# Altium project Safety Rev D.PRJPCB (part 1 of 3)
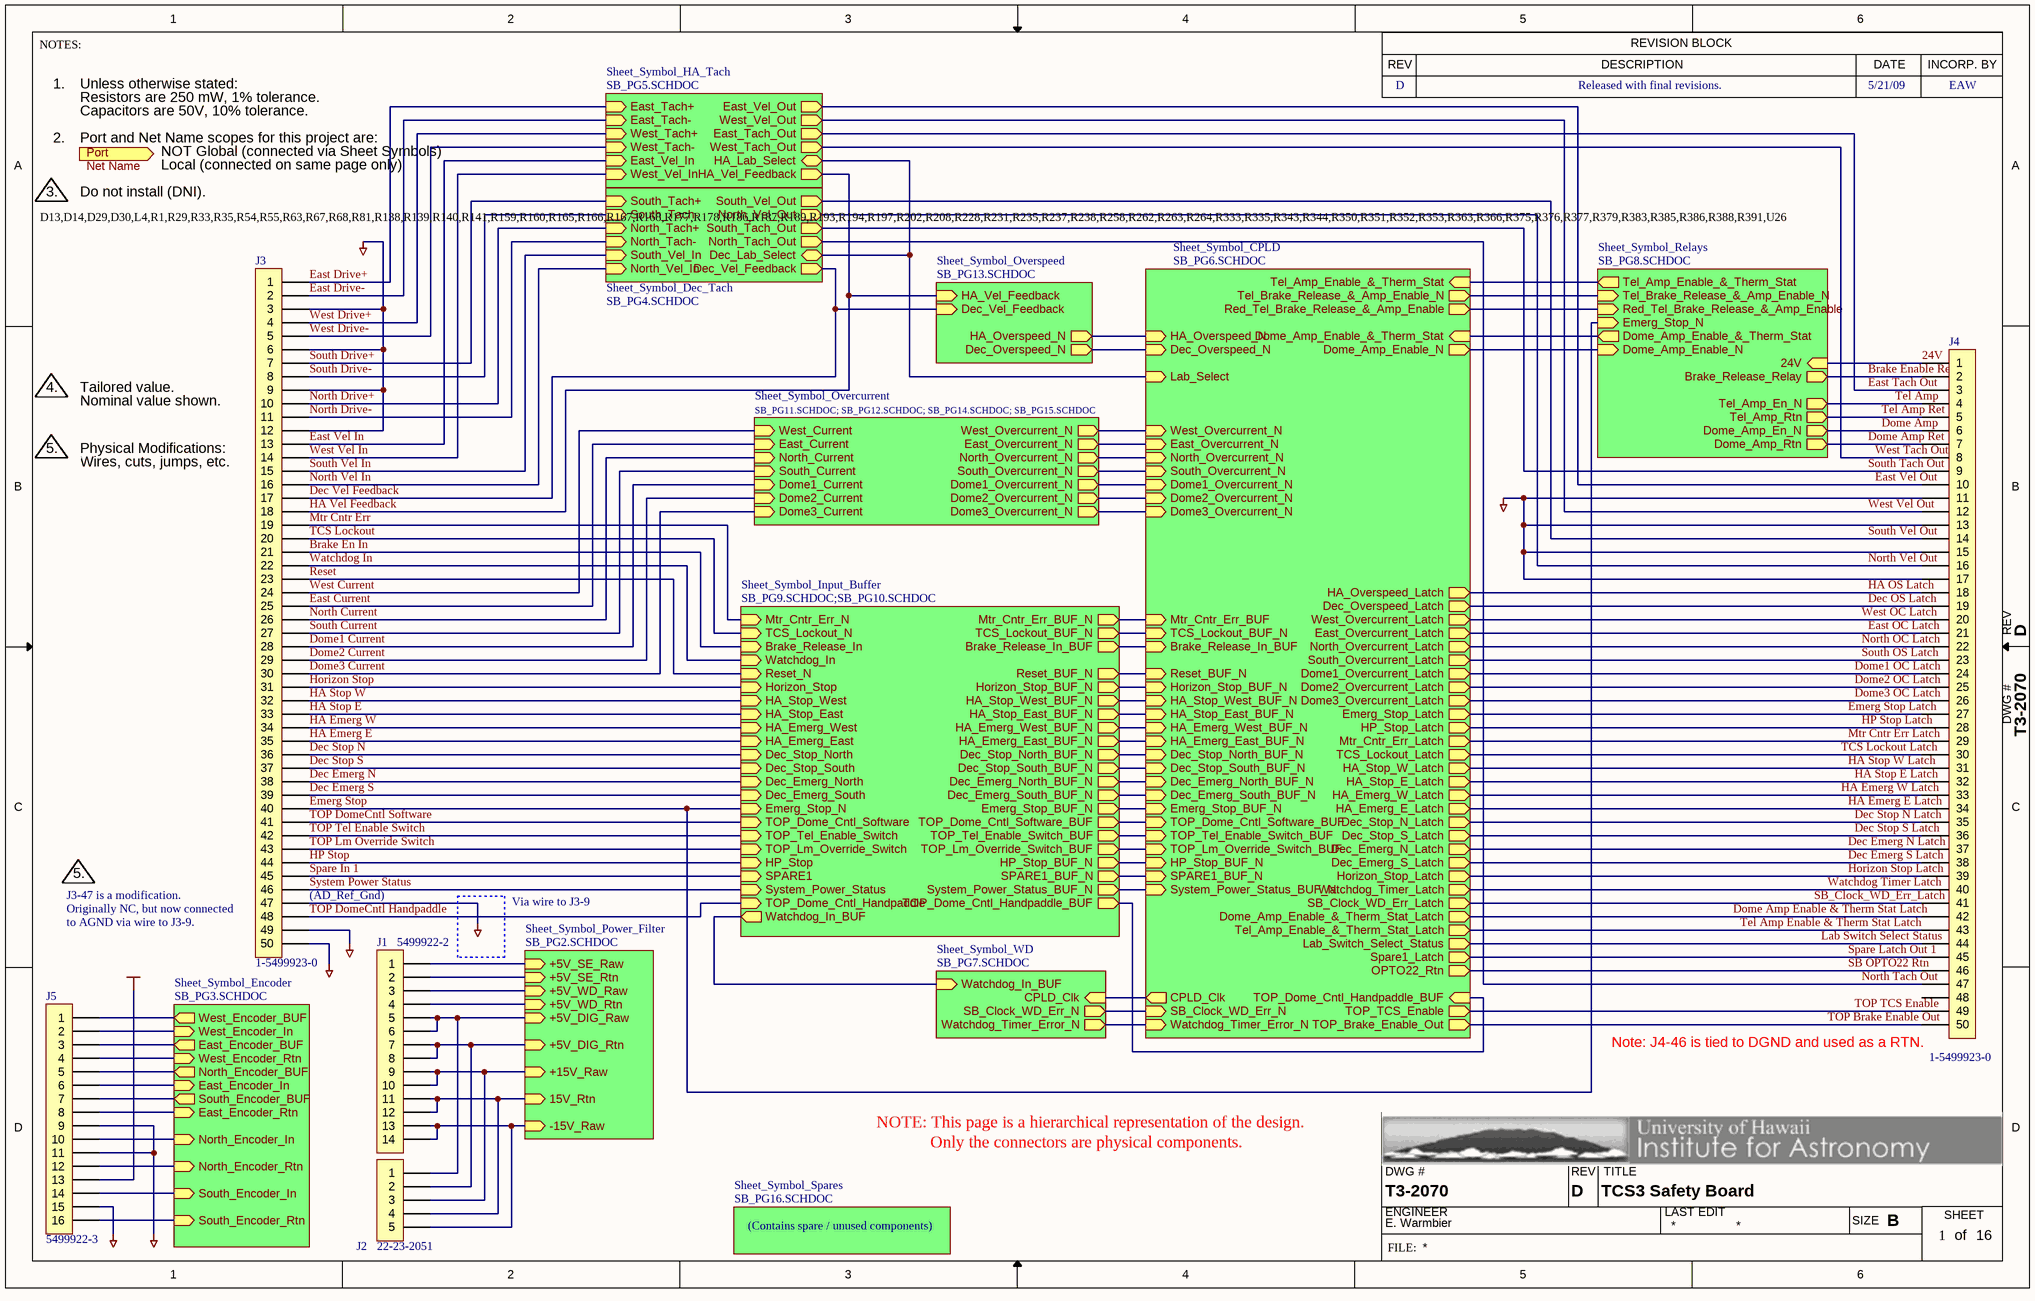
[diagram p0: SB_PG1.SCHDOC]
16 sheets, 769 parts. Net scope: hierarchical (ports join the sheet entries above them; power ports are global).
Board files: Safety_Board_PCB_Rev_D.PcbDoc, Safety_Board_PCB_Rev_D_Fab_Des.PcbDoc
Sheets:
  SB_PG1.SCHDOC
    Sheet_Symbol_Dec_Tach = SB_PG4.SCHDOC
    Sheet_Symbol_Overspeed = SB_PG13.SCHDOC
    Sheet_Symbol_HA_Tach = SB_PG5.SCHDOC
    Sheet_Symbol_CPLD = SB_PG6.SCHDOC
    Sheet_Symbol_Encoder = SB_PG3.SCHDOC
    Sheet_Symbol_Power_Filter = SB_PG2.SCHDOC
    Sheet_Symbol_Overcurrent = SB_PG11.SCHDOC
    Sheet_Symbol_Overcurrent = SB_PG12.SCHDOC
    Sheet_Symbol_Overcurrent = SB_PG14.SCHDOC
    Sheet_Symbol_Overcurrent = SB_PG15.SCHDOC
    Sheet_Symbol_WD = SB_PG7.SCHDOC
    Sheet_Symbol_Relays = SB_PG8.SCHDOC
    Sheet_Symbol_Input_Buffer = SB_PG9.SCHDOC
    Sheet_Symbol_Input_Buffer = SB_PG10.SCHDOC
    Sheet_Symbol_Spares = SB_PG16.SCHDOC

## Sheet SB_PG1.SCHDOC: TCS3 Safety Board
size B; PageSetup: Record=PageOptions|CenterHorizontal=True|CenterVertical=True|PrintScale=0.77|XCorrection=1.00|YCorrection=1.00|PrintKind=0|BorderSize=5000000|LeftOffset=0|BottomOffset=0|Orientation=2|PaperLength=1000|PaperWidth=1000|Scale=100|PaperSource=7|PrintQuality=-4|MediaType=1|DitherType=10|PaperKind=11x17|PrintScaleMode=1; Engineer: E. Warmbier; Organization: Institute for Astronomy; Address1: 640 N. Aohoku Place; Address2: Hilo, HI 96720; DocumentNumber: T3-2070; Revision: D; SheetNumber: 1; SheetTotal: 16

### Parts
(Parts that share a designator on the sheet are numbered #1, #2 ... from top to bottom, then left to right.)
J1  Header_14_(7X2)_STR_SHD_LATCH_col1  [5499922-2]  (value not drawn)
J2  *  [22-23-2051]  (value not drawn)
J3  Header_50_(25X2)_STR_SHD_LATCH_col1  [1-5499923-0]  (value not drawn)
J4  Header_50_(25X2)_STR_SHD_LATCH_col1  [1-5499923-0]  (value not drawn)
J5  Header_16_(8X2)_STR_SHD_LATCH_col1  [5499922-3]  (value not drawn)
Note?#1  Note_1  (value not drawn)  (graphical)
Note?#2  Line2: NOT Global (connected via Sheet Symbols)  Line3: Local (connected on same page only)  Note#: 2.  (hidden comment: Port_Net_Note)  (graphical)
Note?#3  Line1: Do not install (DNI).  Note#: 3.  (hidden comment: Note_Flag)  (graphical)
Note?#4  Line1: Tailored value.  Line2: Nominal value shown.  Note#: 4.  (hidden comment: Note_Flag)  (graphical)
Note?#5  Line1: Physical Modifications:  Line2: Wires, cuts, jumps, etc.  Note#: 5.  (hidden comment: Note_Flag)  (graphical)
Note?#6  Note#: 5.  (hidden comment: Note_Flag)  (graphical)

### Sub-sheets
Sheet_Symbol_CPLD = SB_PG6.SCHDOC: Horizon_Stop_Latch (out), Watchdog_Timer_Latch (out), SB_Clock_WD_Err_N (in), Emerg_Stop_BUF_N (in), Mtr_Cntr_Err_BUF (in), SB_Clock_WD_Err_Latch (out), Dome1_Overcurrent_N (in), Dome2_Overcurrent_N (in), Dome3_Overcurrent_N (in), South_Overcurrent_N (in), Dome_Amp_Enable_&_Therm_Stat_Latch (out), Tel_Amp_Enable_&_Therm_Stat_Latch (out), TCS_Lockout_BUF_N (in), TOP_Dome_Cntl_Software_BUF (in), Horizon_Stop_BUF_N (in), Dec_Emerg_North_BUF_N (in), Dec_Stop_North_BUF_N (in), HA_Stop_East_BUF_N (in), HA_Emerg_West_BUF_N (in), Dec_Emerg_South_BUF_N (in), Dec_Stop_South_BUF_N (in), HA_Stop_West_BUF_N (in), HA_Emerg_East_BUF_N (in), TOP_Lm_Override_Switch_BUF (in), Dome_Amp_Enable_N (out), Brake_Release_In_BUF (in), TOP_Brake_Enable_Out (out), Reset_BUF_N (in), Tel_Brake_Release_&_Amp_Enable_N (out), TOP_Tel_Enable_Switch_BUF (in), TOP_TCS_Enable (out), HP_Stop_BUF_N (in), HA_Overspeed_N (in), Dec_Overspeed_N (in), West_Overcurrent_N (in), East_Overcurrent_N (in), North_Overcurrent_N (in), HA_Overspeed_Latch (out), Dec_Overspeed_Latch (out), West_Overcurrent_Latch (out), East_Overcurrent_Latch (out), North_Overcurrent_Latch (out), South_Overcurrent_Latch (out), Dome1_Overcurrent_Latch (out), Dome2_Overcurrent_Latch (out), Dome3_Overcurrent_Latch (out), Emerg_Stop_Latch (out), HP_Stop_Latch (out), Mtr_Cntr_Err_Latch (out), TCS_Lockout_Latch (out), HA_Stop_W_Latch (out), HA_Stop_E_Latch (out), HA_Emerg_W_Latch (out), HA_Emerg_E_Latch (out), Dec_Stop_N_Latch (out), Dec_Stop_S_Latch (out), Dec_Emerg_N_Latch (out), Dec_Emerg_S_Latch (out), SPARE1_BUF_N (in), System_Power_Status_BUF_N (in), Spare1_Latch (out), TOP_Dome_Cntl_Handpaddle_BUF (in), Watchdog_Timer_Error_N (in), CPLD_Clk (out), Red_Tel_Brake_Release_&_Amp_Enable (out), Lab_Select (in), Tel_Amp_Enable_&_Therm_Stat (in), Dome_Amp_Enable_&_Therm_Stat (in), Lab_Switch_Select_Status (out), OPTO22_Rtn (out)
Sheet_Symbol_Dec_Tach = SB_PG4.SCHDOC: South_Tach+ (in), South_Tach- (in), North_Tach+ (in), North_Tach- (in), South_Vel_In (in), North_Vel_In (in), Dec_Vel_Feedback (out), South_Vel_Out (out), North_Vel_Out (out), North_Tach_Out (out), South_Tach_Out (out), Dec_Lab_Select (bidir)
Sheet_Symbol_Encoder = SB_PG3.SCHDOC: West_Encoder_BUF (out), West_Encoder_In (in), East_Encoder_BUF (out), West_Encoder_Rtn (in), North_Encoder_BUF (out), East_Encoder_In (in), South_Encoder_BUF (out), East_Encoder_Rtn (in), North_Encoder_In (in), North_Encoder_Rtn (in), South_Encoder_In (in), South_Encoder_Rtn (in)
Sheet_Symbol_HA_Tach = SB_PG5.SCHDOC: East_Tach+ (in), East_Tach- (in), West_Tach+ (in), West_Tach- (in), East_Vel_In (in), West_Vel_In (in), HA_Vel_Feedback (out), East_Vel_Out (out), West_Vel_Out (out), East_Tach_Out (out), West_Tach_Out (out), HA_Lab_Select (bidir)
Sheet_Symbol_Input_Buffer = SB_PG9.SCHDOC;SB_PG10.SCHDOC: Mtr_Cntr_Err_N (in), TCS_Lockout_N (in), Brake_Release_In (in), Watchdog_In (in), Reset_N (in), Horizon_Stop (in), HA_Stop_West (in), HA_Stop_East (in), HA_Emerg_West (in), HA_Emerg_East (in), Dec_Stop_North (in), Dec_Stop_South (in), Dec_Emerg_North (in), Dec_Emerg_South (in), Emerg_Stop_N (in), TOP_Dome_Cntl_Software (in), TOP_Tel_Enable_Switch (in), TOP_Lm_Override_Switch (in), HP_Stop (in), SPARE1 (in), System_Power_Status (in), Mtr_Cntr_Err_BUF_N (out), TCS_Lockout_BUF_N (out), Brake_Release_In_BUF (out), Watchdog_In_BUF (out), Reset_BUF_N (out), Horizon_Stop_BUF_N (out), HA_Stop_West_BUF_N (out), HA_Stop_East_BUF_N (out), HA_Emerg_West_BUF_N (out), HA_Emerg_East_BUF_N (out), Dec_Stop_North_BUF_N (out), Dec_Stop_South_BUF_N (out), Dec_Emerg_North_BUF_N (out), Dec_Emerg_South_BUF_N (out), Emerg_Stop_BUF_N (out), TOP_Dome_Cntl_Software_BUF (out), TOP_Tel_Enable_Switch_BUF (out), TOP_Lm_Override_Switch_BUF (out), HP_Stop_BUF_N (out), SPARE1_BUF_N (out), System_Power_Status_BUF_N (out), TOP_Dome_Cntl_Handpaddle (in), TOP_Dome_Cntl_Handpaddle_BUF (out)
Sheet_Symbol_Overcurrent = SB_PG11.SCHDOC; SB_PG12.SCHDOC; SB_PG14.SCHDOC; SB_PG15.SCHDOC: West_Current (in), East_Current (in), North_Current (in), South_Current (in), West_Overcurrent_N (out), East_Overcurrent_N (out), North_Overcurrent_N (out), South_Overcurrent_N (out), Dome1_Overcurrent_N (out), Dome2_Overcurrent_N (out), Dome3_Overcurrent_N (out), Dome1_Current (in), Dome2_Current (in), Dome3_Current (in)
Sheet_Symbol_Overspeed = SB_PG13.SCHDOC: HA_Vel_Feedback (in), Dec_Vel_Feedback (in), HA_Overspeed_N (out), Dec_Overspeed_N (out)
Sheet_Symbol_Power_Filter = SB_PG2.SCHDOC: +5V_SE_Raw (in), +5V_SE_Rtn (in), +5V_WD_Raw (in), +5V_WD_Rtn (in), +5V_DIG_Raw (in), +5V_DIG_Rtn (in), +15V_Raw (in), 15V_Rtn (in), -15V_Raw (in)
Sheet_Symbol_Relays = SB_PG8.SCHDOC: Tel_Amp_Enable_&_Therm_Stat (out), Tel_Brake_Release_&_Amp_Enable_N (in), Red_Tel_Brake_Release_&_Amp_Enable (in), Emerg_Stop_N (in), Dome_Amp_Rtn (out), Dome_Amp_En_N (out), Brake_Release_Relay (out), Tel_Amp_Rtn (out), 24V (in), Dome_Amp_Enable_&_Therm_Stat (out), Tel_Amp_En_N (out), Dome_Amp_Enable_N (in)
Sheet_Symbol_Spares = SB_PG16.SCHDOC: no entries
Sheet_Symbol_WD = SB_PG7.SCHDOC: CPLD_Clk (in), Watchdog_In_BUF (in), SB_Clock_WD_Err_N (out), Watchdog_Timer_Error_N (out)

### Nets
24VGND: J3.49
+5V_DIG: J5.13
AGND: J3.3 J3.6 J3.9 J3.12 J3.47 J4.11 J4.13 J4.15 J4.17
DGND: J5.15
EGND: J5.9 J5.11
PCGND: J3.50
15V_Rtn: J1.11 J1.12 J2.4 ; sheet Sheet_Symbol_Power_Filter/15V_Rtn
24V: J4.1 ; sheet Sheet_Symbol_Relays/24V
+5V_DIG_Raw: J1.5 J1.6 J2.1 ; sheet Sheet_Symbol_Power_Filter/+5V_DIG_Raw
+5V_DIG_Rtn: J1.7 J1.8 J2.2 ; sheet Sheet_Symbol_Power_Filter/+5V_DIG_Rtn
+5V_SE_Raw: J1.1 ; sheet Sheet_Symbol_Power_Filter/+5V_SE_Raw
+5V_SE_Rtn: J1.2 ; sheet Sheet_Symbol_Power_Filter/+5V_SE_Rtn
+5V_WD_Raw: J1.3 ; sheet Sheet_Symbol_Power_Filter/+5V_WD_Raw
+5V_WD_Rtn: J1.4 ; sheet Sheet_Symbol_Power_Filter/+5V_WD_Rtn
+15V_Raw: J1.9 J1.10 J2.3 ; sheet Sheet_Symbol_Power_Filter/+15V_Raw
-15V_Raw: J1.13 J1.14 J2.5 ; sheet Sheet_Symbol_Power_Filter/-15V_Raw
Brake En In: J3.21 ; sheet Sheet_Symbol_Input_Buffer/Brake_Release_In
Brake Enable Relay: J4.2 ; sheet Sheet_Symbol_Relays/Brake_Release_Relay
Brake_Release_In_BUF: sheet Sheet_Symbol_CPLD/Brake_Release_In_BUF, sheet Sheet_Symbol_Input_Buffer/Brake_Release_In_BUF
CPLD_Clk: sheet Sheet_Symbol_CPLD/CPLD_Clk, sheet Sheet_Symbol_WD/CPLD_Clk
Dec Emerg N: J3.38 ; sheet Sheet_Symbol_Input_Buffer/Dec_Emerg_North
Dec Emerg N Latch: J4.37 ; sheet Sheet_Symbol_CPLD/Dec_Emerg_N_Latch
Dec Emerg S: J3.39 ; sheet Sheet_Symbol_Input_Buffer/Dec_Emerg_South
Dec Emerg S Latch: J4.38 ; sheet Sheet_Symbol_CPLD/Dec_Emerg_S_Latch
Dec OS Latch: J4.19 ; sheet Sheet_Symbol_CPLD/Dec_Overspeed_Latch
Dec Stop N: J3.36 ; sheet Sheet_Symbol_Input_Buffer/Dec_Stop_North
Dec Stop N Latch: J4.35 ; sheet Sheet_Symbol_CPLD/Dec_Stop_N_Latch
Dec Stop S: J3.37 ; sheet Sheet_Symbol_Input_Buffer/Dec_Stop_South
Dec Stop S Latch: J4.36 ; sheet Sheet_Symbol_CPLD/Dec_Stop_S_Latch
Dec Vel Feedback: J3.17 ; sheet Sheet_Symbol_Dec_Tach/Dec_Vel_Feedback, sheet Sheet_Symbol_Overspeed/Dec_Vel_Feedback
Dec_Emerg_North_BUF_N: sheet Sheet_Symbol_CPLD/Dec_Emerg_North_BUF_N, sheet Sheet_Symbol_Input_Buffer/Dec_Emerg_North_BUF_N
Dec_Emerg_South_BUF_N: sheet Sheet_Symbol_CPLD/Dec_Emerg_South_BUF_N, sheet Sheet_Symbol_Input_Buffer/Dec_Emerg_South_BUF_N
Dec_Lab_Select: sheet Sheet_Symbol_Dec_Tach/Dec_Lab_Select, sheet Sheet_Symbol_HA_Tach/HA_Lab_Select, sheet Sheet_Symbol_CPLD/Lab_Select
Dec_Overspeed_N: sheet Sheet_Symbol_Overspeed/Dec_Overspeed_N, sheet Sheet_Symbol_CPLD/Dec_Overspeed_N
Dec_Stop_North_BUF_N: sheet Sheet_Symbol_CPLD/Dec_Stop_North_BUF_N, sheet Sheet_Symbol_Input_Buffer/Dec_Stop_North_BUF_N
Dec_Stop_South_BUF_N: sheet Sheet_Symbol_CPLD/Dec_Stop_South_BUF_N, sheet Sheet_Symbol_Input_Buffer/Dec_Stop_South_BUF_N
Dome1 Current: J3.28 ; sheet Sheet_Symbol_Overcurrent/Dome1_Current
Dome1 OC Latch: J4.24 ; sheet Sheet_Symbol_CPLD/Dome1_Overcurrent_Latch
Dome1_Overcurrent_N: sheet Sheet_Symbol_CPLD/Dome1_Overcurrent_N, sheet Sheet_Symbol_Overcurrent/Dome1_Overcurrent_N
Dome2 Current: J3.29 ; sheet Sheet_Symbol_Overcurrent/Dome2_Current
Dome2 OC Latch: J4.25 ; sheet Sheet_Symbol_CPLD/Dome2_Overcurrent_Latch
Dome2_Overcurrent_N: sheet Sheet_Symbol_CPLD/Dome2_Overcurrent_N, sheet Sheet_Symbol_Overcurrent/Dome2_Overcurrent_N
Dome3 Current: J3.30 ; sheet Sheet_Symbol_Overcurrent/Dome3_Current
Dome3 OC Latch: J4.26 ; sheet Sheet_Symbol_CPLD/Dome3_Overcurrent_Latch
Dome3_Overcurrent_N: sheet Sheet_Symbol_CPLD/Dome3_Overcurrent_N, sheet Sheet_Symbol_Overcurrent/Dome3_Overcurrent_N
Dome Amp: J4.6 ; sheet Sheet_Symbol_Relays/Dome_Amp_En_N
Dome Amp Enable & Therm Stat Latch: J4.42 ; sheet Sheet_Symbol_CPLD/Dome_Amp_Enable_&_Therm_Stat_Latch
Dome Amp Ret: J4.7 ; sheet Sheet_Symbol_Relays/Dome_Amp_Rtn
Dome_Amp_Enable_&_Therm_Stat: sheet Sheet_Symbol_CPLD/Dome_Amp_Enable_&_Therm_Stat, sheet Sheet_Symbol_Relays/Dome_Amp_Enable_&_Therm_Stat
Dome_Amp_Enable_N: sheet Sheet_Symbol_CPLD/Dome_Amp_Enable_N, sheet Sheet_Symbol_Relays/Dome_Amp_Enable_N
East Current: J3.25 ; sheet Sheet_Symbol_Overcurrent/East_Current
East Drive+: J3.1 ; sheet Sheet_Symbol_HA_Tach/East_Tach+
East Drive-: J3.2 ; sheet Sheet_Symbol_HA_Tach/East_Tach-
East OC Latch: J4.21 ; sheet Sheet_Symbol_CPLD/East_Overcurrent_Latch
East Tach Out: J4.3 ; sheet Sheet_Symbol_HA_Tach/East_Tach_Out
East Vel In: J3.13 ; sheet Sheet_Symbol_HA_Tach/East_Vel_In
East Vel Out: J4.10 ; sheet Sheet_Symbol_HA_Tach/East_Vel_Out
East_Encoder_BUF: J5.3 ; sheet Sheet_Symbol_Encoder/East_Encoder_BUF
East_Encoder_In: J5.6 ; sheet Sheet_Symbol_Encoder/East_Encoder_In
East_Encoder_Rtn: J5.8 ; sheet Sheet_Symbol_Encoder/East_Encoder_Rtn
East_Overcurrent_N: sheet Sheet_Symbol_CPLD/East_Overcurrent_N, sheet Sheet_Symbol_Overcurrent/East_Overcurrent_N
Emerg Stop: J3.40 ; sheet Sheet_Symbol_Relays/Emerg_Stop_N, sheet Sheet_Symbol_Input_Buffer/Emerg_Stop_N
Emerg Stop Latch: J4.27 ; sheet Sheet_Symbol_CPLD/Emerg_Stop_Latch
Emerg_Stop_BUF_N: sheet Sheet_Symbol_CPLD/Emerg_Stop_BUF_N, sheet Sheet_Symbol_Input_Buffer/Emerg_Stop_BUF_N
HA Emerg E: J3.35 ; sheet Sheet_Symbol_Input_Buffer/HA_Emerg_East
HA Emerg E Latch: J4.34 ; sheet Sheet_Symbol_CPLD/HA_Emerg_E_Latch
HA Emerg W: J3.34 ; sheet Sheet_Symbol_Input_Buffer/HA_Emerg_West
HA Emerg W Latch: J4.33 ; sheet Sheet_Symbol_CPLD/HA_Emerg_W_Latch
HA OS Latch: J4.18 ; sheet Sheet_Symbol_CPLD/HA_Overspeed_Latch
HA Stop E: J3.33 ; sheet Sheet_Symbol_Input_Buffer/HA_Stop_East
HA Stop E Latch: J4.32 ; sheet Sheet_Symbol_CPLD/HA_Stop_E_Latch
HA Stop W: J3.32 ; sheet Sheet_Symbol_Input_Buffer/HA_Stop_West
HA Stop W Latch: J4.31 ; sheet Sheet_Symbol_CPLD/HA_Stop_W_Latch
HA Vel Feedback: J3.18 ; sheet Sheet_Symbol_Overspeed/HA_Vel_Feedback, sheet Sheet_Symbol_HA_Tach/HA_Vel_Feedback
HA_Emerg_East_BUF_N: sheet Sheet_Symbol_CPLD/HA_Emerg_East_BUF_N, sheet Sheet_Symbol_Input_Buffer/HA_Emerg_East_BUF_N
HA_Emerg_West_BUF_N: sheet Sheet_Symbol_CPLD/HA_Emerg_West_BUF_N, sheet Sheet_Symbol_Input_Buffer/HA_Emerg_West_BUF_N
HA_Overspeed_N: sheet Sheet_Symbol_Overspeed/HA_Overspeed_N, sheet Sheet_Symbol_CPLD/HA_Overspeed_N
HA_Stop_East_BUF_N: sheet Sheet_Symbol_CPLD/HA_Stop_East_BUF_N, sheet Sheet_Symbol_Input_Buffer/HA_Stop_East_BUF_N
HA_Stop_West_BUF_N: sheet Sheet_Symbol_CPLD/HA_Stop_West_BUF_N, sheet Sheet_Symbol_Input_Buffer/HA_Stop_West_BUF_N
Horizon Stop: J3.31 ; sheet Sheet_Symbol_Input_Buffer/Horizon_Stop
Horizon Stop Latch: J4.39 ; sheet Sheet_Symbol_CPLD/Horizon_Stop_Latch
Horizon_Stop_BUF_N: sheet Sheet_Symbol_CPLD/Horizon_Stop_BUF_N, sheet Sheet_Symbol_Input_Buffer/Horizon_Stop_BUF_N
HP Stop: J3.44 ; sheet Sheet_Symbol_Input_Buffer/HP_Stop
HP Stop Latch: J4.28 ; sheet Sheet_Symbol_CPLD/HP_Stop_Latch
HP_Stop_BUF_N: sheet Sheet_Symbol_CPLD/HP_Stop_BUF_N, sheet Sheet_Symbol_Input_Buffer/HP_Stop_BUF_N
Lab Switch Select Status: J4.44 ; sheet Sheet_Symbol_CPLD/Lab_Switch_Select_Status
Mtr Cntr Err: J3.19 ; sheet Sheet_Symbol_Input_Buffer/Mtr_Cntr_Err_N
Mtr Cntr Err Latch: J4.29 ; sheet Sheet_Symbol_CPLD/Mtr_Cntr_Err_Latch
Mtr_Cntr_Err_BUF: sheet Sheet_Symbol_CPLD/Mtr_Cntr_Err_BUF, sheet Sheet_Symbol_Input_Buffer/Mtr_Cntr_Err_BUF_N
North Current: J3.26 ; sheet Sheet_Symbol_Overcurrent/North_Current
North Drive+: J3.10 ; sheet Sheet_Symbol_Dec_Tach/North_Tach+
North Drive-: J3.11 ; sheet Sheet_Symbol_Dec_Tach/North_Tach-
North OC Latch: J4.22 ; sheet Sheet_Symbol_CPLD/North_Overcurrent_Latch
North Tach Out: J4.47 ; sheet Sheet_Symbol_Dec_Tach/North_Tach_Out
North Vel In: J3.16 ; sheet Sheet_Symbol_Dec_Tach/North_Vel_In
North Vel Out: J4.16 ; sheet Sheet_Symbol_Dec_Tach/North_Vel_Out
North_Encoder_BUF: J5.5 ; sheet Sheet_Symbol_Encoder/North_Encoder_BUF
North_Encoder_In: J5.10 ; sheet Sheet_Symbol_Encoder/North_Encoder_In
North_Encoder_Rtn: J5.12 ; sheet Sheet_Symbol_Encoder/North_Encoder_Rtn
North_Overcurrent_N: sheet Sheet_Symbol_CPLD/North_Overcurrent_N, sheet Sheet_Symbol_Overcurrent/North_Overcurrent_N
Red_Tel_Brake_Release_&_Amp_Enable: sheet Sheet_Symbol_CPLD/Red_Tel_Brake_Release_&_Amp_Enable, sheet Sheet_Symbol_Relays/Red_Tel_Brake_Release_&_Amp_Enable
Reset: J3.23 ; sheet Sheet_Symbol_Input_Buffer/Reset_N
Reset_BUF_N: sheet Sheet_Symbol_CPLD/Reset_BUF_N, sheet Sheet_Symbol_Input_Buffer/Reset_BUF_N
SB OPTO22 Rtn: J4.46 ; sheet Sheet_Symbol_CPLD/OPTO22_Rtn
SB_Clock_WD_Err_Latch: J4.41 ; sheet Sheet_Symbol_CPLD/SB_Clock_WD_Err_Latch
SB_Clock_WD_Err_N: sheet Sheet_Symbol_CPLD/SB_Clock_WD_Err_N, sheet Sheet_Symbol_WD/SB_Clock_WD_Err_N
South Current: J3.27 ; sheet Sheet_Symbol_Overcurrent/South_Current
South Drive+: J3.7 ; sheet Sheet_Symbol_Dec_Tach/South_Tach+
South Drive-: J3.8 ; sheet Sheet_Symbol_Dec_Tach/South_Tach-
South OS Latch: J4.23 ; sheet Sheet_Symbol_CPLD/South_Overcurrent_Latch
South Tach Out: J4.9 ; sheet Sheet_Symbol_Dec_Tach/South_Tach_Out
South Vel In: J3.15 ; sheet Sheet_Symbol_Dec_Tach/South_Vel_In
South Vel Out: J4.14 ; sheet Sheet_Symbol_Dec_Tach/South_Vel_Out
South_Encoder_BUF: J5.7 ; sheet Sheet_Symbol_Encoder/South_Encoder_BUF
South_Encoder_In: J5.14 ; sheet Sheet_Symbol_Encoder/South_Encoder_In
South_Encoder_Rtn: J5.16 ; sheet Sheet_Symbol_Encoder/South_Encoder_Rtn
South_Overcurrent_N: sheet Sheet_Symbol_CPLD/South_Overcurrent_N, sheet Sheet_Symbol_Overcurrent/South_Overcurrent_N
SPARE1_BUF_N: sheet Sheet_Symbol_CPLD/SPARE1_BUF_N, sheet Sheet_Symbol_Input_Buffer/SPARE1_BUF_N
Spare In 1: J3.45 ; sheet Sheet_Symbol_Input_Buffer/SPARE1
Spare Latch Out 1: J4.45 ; sheet Sheet_Symbol_CPLD/Spare1_Latch
System Power Status: J3.46 ; sheet Sheet_Symbol_Input_Buffer/System_Power_Status
System_Power_Status_BUF_N: sheet Sheet_Symbol_CPLD/System_Power_Status_BUF_N, sheet Sheet_Symbol_Input_Buffer/System_Power_Status_BUF_N
TCS Lockout: J3.20 ; sheet Sheet_Symbol_Input_Buffer/TCS_Lockout_N
TCS Lockout Latch: J4.30 ; sheet Sheet_Symbol_CPLD/TCS_Lockout_Latch
TCS_Lockout_BUF_N: sheet Sheet_Symbol_CPLD/TCS_Lockout_BUF_N, sheet Sheet_Symbol_Input_Buffer/TCS_Lockout_BUF_N
Tel Amp: J4.4 ; sheet Sheet_Symbol_Relays/Tel_Amp_En_N
Tel Amp Enable & Therm Stat Latch: J4.43 ; sheet Sheet_Symbol_CPLD/Tel_Amp_Enable_&_Therm_Stat_Latch
Tel Amp Ret: J4.5 ; sheet Sheet_Symbol_Relays/Tel_Amp_Rtn
Tel_Amp_Enable_&_Therm_Stat: sheet Sheet_Symbol_CPLD/Tel_Amp_Enable_&_Therm_Stat, sheet Sheet_Symbol_Relays/Tel_Amp_Enable_&_Therm_Stat
Tel_Brake_Release_&_Amp_Enable_N: sheet Sheet_Symbol_CPLD/Tel_Brake_Release_&_Amp_Enable_N, sheet Sheet_Symbol_Relays/Tel_Brake_Release_&_Amp_Enable_N
TOP Brake Enable Out: J4.50 ; sheet Sheet_Symbol_CPLD/TOP_Brake_Enable_Out
TOP DomeCntl Handpaddle: J3.48 ; sheet Sheet_Symbol_Input_Buffer/TOP_Dome_Cntl_Handpaddle
TOP DomeCntl Software: J3.41 ; sheet Sheet_Symbol_Input_Buffer/TOP_Dome_Cntl_Software
TOP Lm Override Switch: J3.43 ; sheet Sheet_Symbol_Input_Buffer/TOP_Lm_Override_Switch
TOP TCS Enable: J4.49 ; sheet Sheet_Symbol_CPLD/TOP_TCS_Enable
TOP Tel Enable Switch: J3.42 ; sheet Sheet_Symbol_Input_Buffer/TOP_Tel_Enable_Switch
TOP_Dome_Cntl_Handpaddle_BUF: sheet Sheet_Symbol_CPLD/TOP_Dome_Cntl_Handpaddle_BUF, sheet Sheet_Symbol_Input_Buffer/TOP_Dome_Cntl_Handpaddle_BUF
TOP_Dome_Cntl_Software_BUF: sheet Sheet_Symbol_CPLD/TOP_Dome_Cntl_Software_BUF, sheet Sheet_Symbol_Input_Buffer/TOP_Dome_Cntl_Software_BUF
TOP_Lm_Override_Switch_BUF: sheet Sheet_Symbol_CPLD/TOP_Lm_Override_Switch_BUF, sheet Sheet_Symbol_Input_Buffer/TOP_Lm_Override_Switch_BUF
TOP_Tel_Enable_Switch_BUF: sheet Sheet_Symbol_CPLD/TOP_Tel_Enable_Switch_BUF, sheet Sheet_Symbol_Input_Buffer/TOP_Tel_Enable_Switch_BUF
Watchdog In: J3.22 ; sheet Sheet_Symbol_Input_Buffer/Watchdog_In
Watchdog Timer Latch: J4.40 ; sheet Sheet_Symbol_CPLD/Watchdog_Timer_Latch
Watchdog_In_BUF: sheet Sheet_Symbol_WD/Watchdog_In_BUF, sheet Sheet_Symbol_Input_Buffer/Watchdog_In_BUF
Watchdog_Timer_Error_N: sheet Sheet_Symbol_CPLD/Watchdog_Timer_Error_N, sheet Sheet_Symbol_WD/Watchdog_Timer_Error_N
West Current: J3.24 ; sheet Sheet_Symbol_Overcurrent/West_Current
West Drive+: J3.4 ; sheet Sheet_Symbol_HA_Tach/West_Tach+
West Drive-: J3.5 ; sheet Sheet_Symbol_HA_Tach/West_Tach-
West OC Latch: J4.20 ; sheet Sheet_Symbol_CPLD/West_Overcurrent_Latch
West Tach Out: J4.8 ; sheet Sheet_Symbol_HA_Tach/West_Tach_Out
West Vel In: J3.14 ; sheet Sheet_Symbol_HA_Tach/West_Vel_In
West Vel Out: J4.12 ; sheet Sheet_Symbol_HA_Tach/West_Vel_Out
West_Encoder_BUF: J5.1 ; sheet Sheet_Symbol_Encoder/West_Encoder_BUF
West_Encoder_In: J5.2 ; sheet Sheet_Symbol_Encoder/West_Encoder_In
West_Encoder_Rtn: J5.4 ; sheet Sheet_Symbol_Encoder/West_Encoder_Rtn
West_Overcurrent_N: sheet Sheet_Symbol_CPLD/West_Overcurrent_N, sheet Sheet_Symbol_Overcurrent/West_Overcurrent_N

Not connected (* = marked no-connect by the designer): J4 48

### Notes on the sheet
- (near Note?#1) NOTES:
- D
- Released with final revisions.
- 5/21/09
- EAW
- (near Note?#4) D13,D14,D29,D30,L4,R1,R29,R33,R35,R54,R55,R63,R67,R68,R81,R138,R139,R140,R141,R159,R160,R165,R166,R167,R168,R177,R178,R186,R187,R189,R193,R194,R197,R202,R208,R228,R231,R235,R237,R238,R258,R262,R263,R264,R333,R335,R343,R344,R350,R351,R352,R353,R363,R366,R375,R376,R377,R379,R383,R385,R386,R388,R391,U26
- (near Note?#6) J3-47 is a modification.
- (near J3) Originally NC, but now connected
- (near J3) (AD_Ref_Gnd)
- Via wire to J3-9
- to AGND via wire to J3-9.
- (near J4) Note: J4-46 is tied to DGND and used as a RTN.
- NOTE: This page is a hierarchical representation of the design.
- Only the connectors are physical components.
- (Contains spare / unused components)

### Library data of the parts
J1 = Header_14_(7X2)_STR_SHD_LATCH_col1: Header, 14-Pin, Dual row, Straight, Latch, Shroud; Manufacturer: Tyco
J2 = IRTF_STD_POWER: Header, 5 position, single row, male, straight; Manufacturer: Molex/Waldom
J3 J4 = Header_50_(25X2)_STR_SHD_LATCH_col1: Header, 50-Pin, Dual Row, Shrouded, Straight, Male, Shroud; Manufacturer: Tyco
J5 = Header_16_(8X2)_STR_SHD_LATCH_col1: Header, 16-Pin, Dual row, Straight, Latch, Shroud; Manufacturer: Tyco
Note?#1 = Note_1: Note #1
Note?#2 = Port_Net_Note: Port & Net Scope Note
Note?#3 = Note_Flag: Flag Note; Line2: (line 2); Line3: (line 3)
Note?#4 Note?#5 = Note_Flag: Flag Note; Line3: (line 3)
Note?#6 = Note_Flag: Flag Note; Line1: Physical Modifications:; Line2: Wires, cuts, jumps, etc.; Line3: (line 3)

## Sheet SB_PG4.SCHDOC: (Title)
size B; PageSetup: Record=PageOptions|CenterHorizontal=True|CenterVertical=True|PrintScale=0.70|XCorrection=1.00|YCorrection=1.00|PrintKind=0|BorderSize=5000000|LeftOffset=0|BottomOffset=0|Orientation=2|PaperLength=1000|PaperWidth=1000|Scale=100|PaperSource=7|PrintQuality=-4|MediaType=1|DitherType=10|PaperKind=Letter|PrintScaleMode=1; Engineer: (Engineer); Organization: Institute for Astronomy; Address1: 640 N. Aohoku Place; Address2: Hilo, HI 96720; DocumentNumber: T3-2070; Revision: D; SheetNumber: 4; SheetTotal: 16
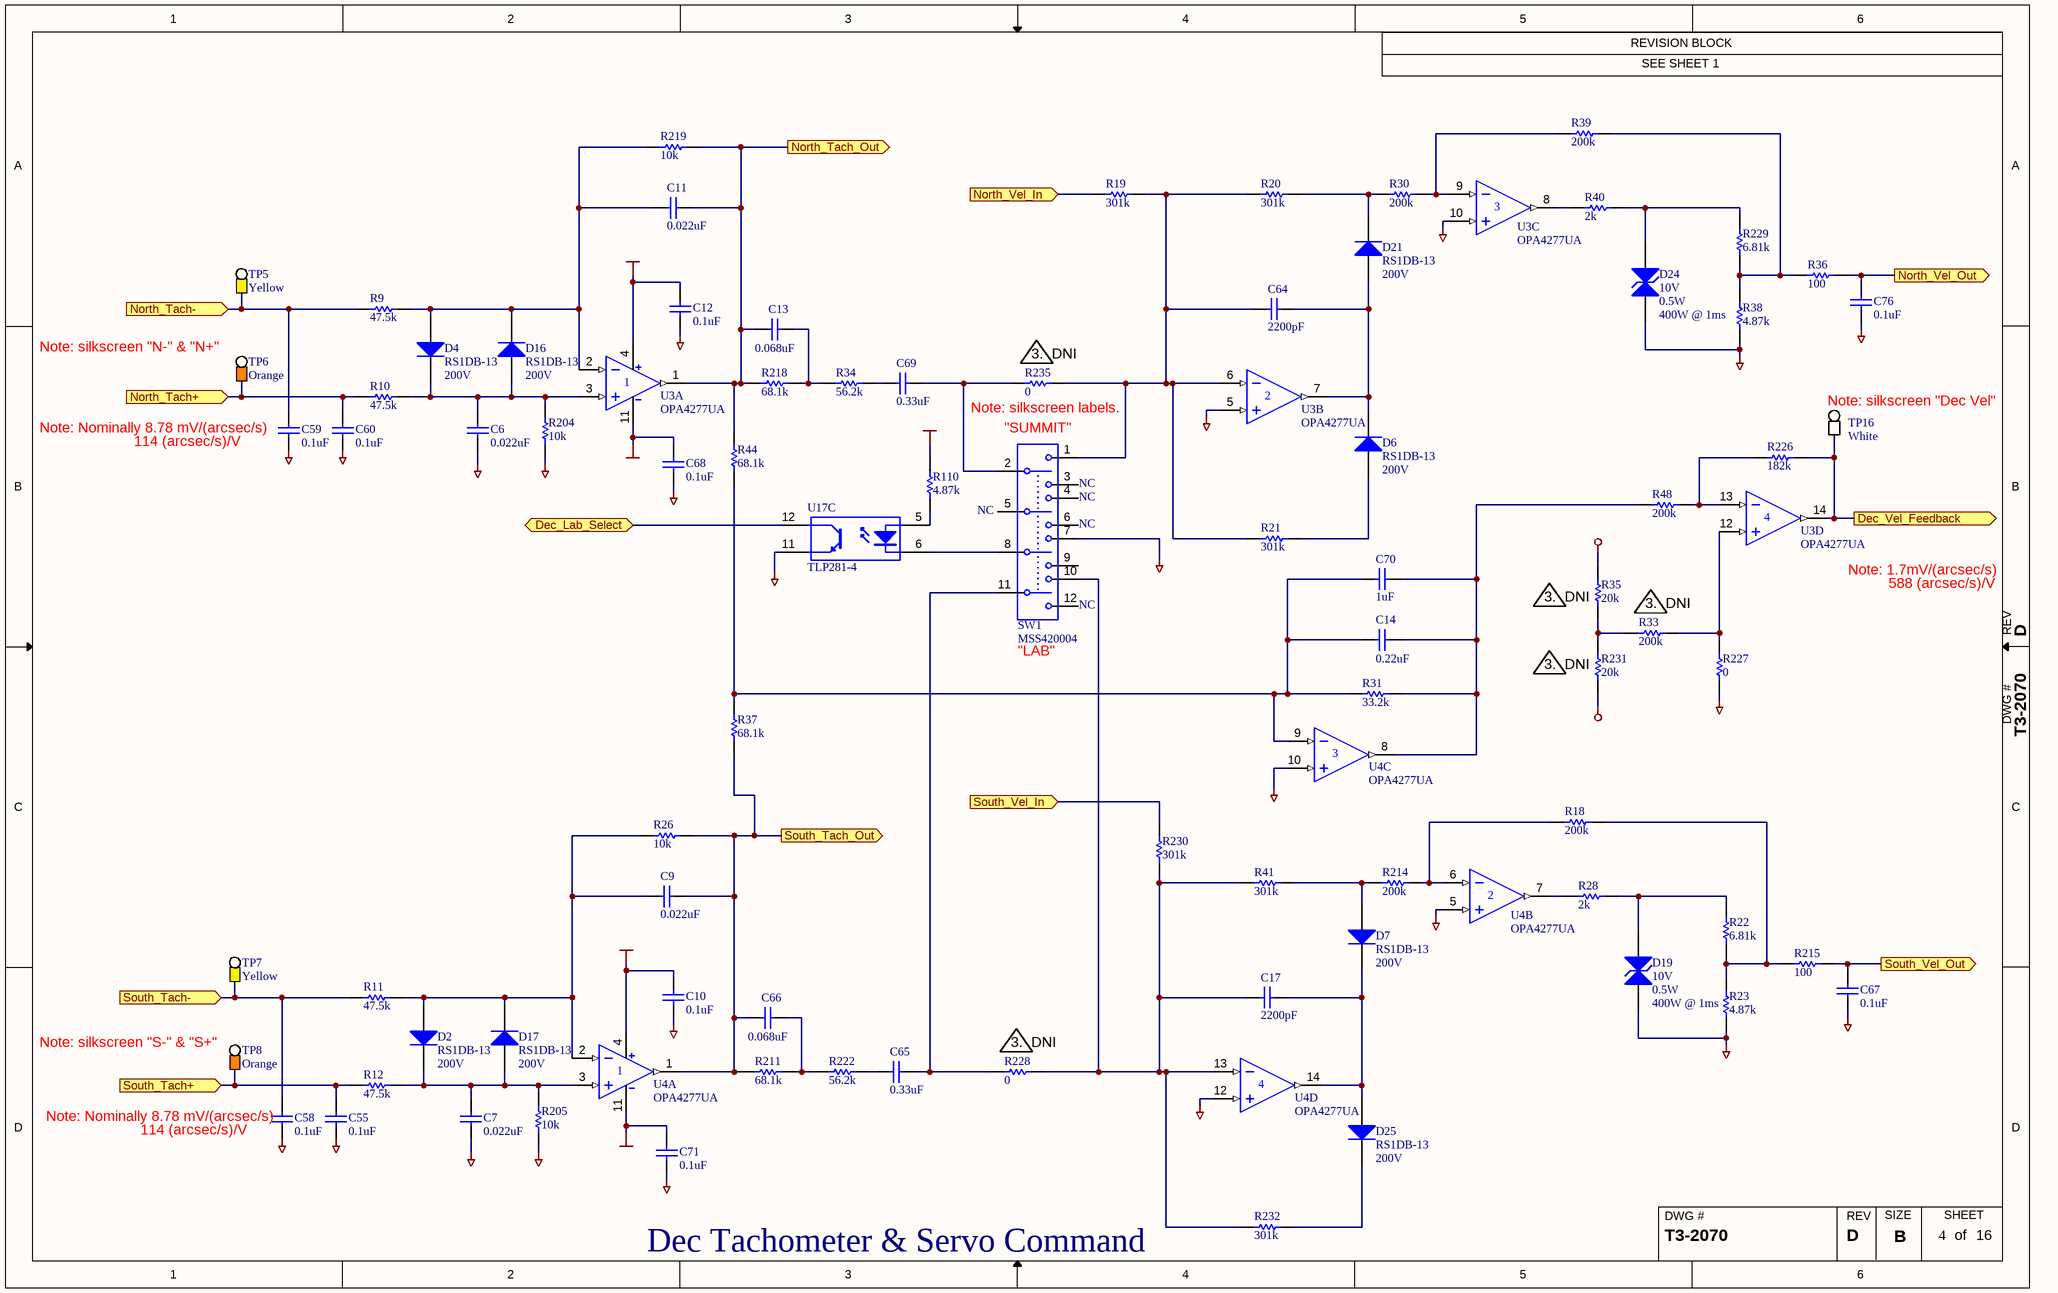
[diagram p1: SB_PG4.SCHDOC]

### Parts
(Parts that share a designator on the sheet are numbered #1, #2 ... from top to bottom, then left to right.)
C6  0.022uF  [1206]
C7  0.022uF  [1206]
C9  0.022uF  [1206]
C10  0.1uF  [1206]
C11  0.022uF  [1206]
C12  0.1uF  [1206]
C13  0.068uF  [1206]
C14  0.22uF  [1206]
C17  2200pF  [1206]
C55  0.1uF  [1206]
C58  0.1uF  [1206]
C59  0.1uF  [1206]
C60  0.1uF  [1206]
C64  2200pF  [1206]
C65  0.33uF  [1206]
C66  0.068uF  [1206]
C67  0.1uF  [1206]
C68  0.1uF  [1206]
C69  0.33uF  [1206]
C70  1uF  [1206]
C71  0.1uF  [1206]
C76  0.1uF  [1206]
D2  Voltage: 200V  [DO-214AA (SMB) & MARKING]  (hidden comment: RS1DB-13)
D4  Voltage: 200V  [DO-214AA (SMB) & MARKING]  (hidden comment: RS1DB-13)
D6  Voltage: 200V  [DO-214AA (SMB) & MARKING]  (hidden comment: RS1DB-13)
D7  Voltage: 200V  [DO-214AA (SMB) & MARKING]  (hidden comment: RS1DB-13)
D16  Voltage: 200V  [DO-214AA (SMB) & MARKING]  (hidden comment: RS1DB-13)
D17  Voltage: 200V  [DO-214AA (SMB) & MARKING]  (hidden comment: RS1DB-13)
D19  value 10V  Power: 0.5W  Peak Power: 400W @ 1ms  [DO-214AC (SMA)]  (hidden comment: 1SMA10CAT3G)
D21  Voltage: 200V  [DO-214AA (SMB) & MARKING]  (hidden comment: RS1DB-13)
D24  value 10V  Power: 0.5W  Peak Power: 400W @ 1ms  [DO-214AC (SMA)]  (hidden comment: 1SMA10CAT3G)
D25  Voltage: 200V  [DO-214AA (SMB) & MARKING]  (hidden comment: RS1DB-13)
Flag?#1  Flag#: 3.  Note: DNI  (graphical)
Flag?#2  Flag#: 3.  Note: DNI  (graphical)
Flag?#3  Flag#: 3.  Note: DNI  (graphical)
Flag?#4  Flag#: 3.  Note: DNI  (graphical)
Flag?#5  Flag#: 3.  Note: DNI  (graphical)
R9  value 47.5k  [1206]  (hidden comment: 47500)
R10  value 47.5k  [1206]  (hidden comment: 47500)
R11  value 47.5k  [1206]  (hidden comment: 47500)
R12  value 47.5k  [1206]  (hidden comment: 47500)
R18  value 200k  [1206]  (hidden comment: 200000)
R19  value 301k  [1206]  (hidden comment: 301000)
R20  value 301k  [1206]  (hidden comment: 301000)
R21  value 301k  [1206]  (hidden comment: 301000)
R22  value 6.81k  [1206]  (hidden comment: 6810)
R23  value 4.87k  [1206]  (hidden comment: 4870)
R26  value 10k  [1206]  (hidden comment: 10000)
R28  value 2k  [1206]  (hidden comment: 2000)
R30  value 200k  [1206]  (hidden comment: 200000)
R31  value 33.2k  [1206]  (hidden comment: 33200)
R33  value 200k  [1206]  (hidden comment: 200000)  (no BOM)
R34  value 56.2k  [1206]  (hidden comment: 56200)
R35  value 20k  [1206]  (hidden comment: 20000)  (no BOM)
R36  100  [1206]
R37  value 68.1k  [1206]  (hidden comment: 68100)
R38  value 4.87k  [1206]  (hidden comment: 4870)
R39  value 200k  [1206]  (hidden comment: 200000)
R40  value 2k  [1206]  (hidden comment: 2000)
R41  value 301k  [1206]  (hidden comment: 301000)
R44  value 68.1k  [1206]  (hidden comment: 68100)
R48  value 200k  [1206]  (hidden comment: 200000)
R110  value 4.87k  [1206]  (hidden comment: 4870)
R204  value 10k  [1206]  (hidden comment: 10000)
R205  value 10k  [1206]  (hidden comment: 10000)
R211  value 68.1k  [1206]  (hidden comment: 68100)
R214  value 200k  [1206]  (hidden comment: 200000)
R215  100  [1206]
R218  value 68.1k  [1206]  (hidden comment: 68100)
R219  value 10k  [1206]  (hidden comment: 10000)
R222  value 56.2k  [1206]  (hidden comment: 56200)
R226  value 182k  [1206]  (hidden comment: 182000)
R227  value 0  [1206]  (hidden comment: 0_jumper)
R228  value 0  [1206]  (hidden comment: 0_jumper)  (no BOM)
R229  value 6.81k  [1206]  (hidden comment: 6810)
R230  value 301k  [1206]  (hidden comment: 301000)
R231  value 20k  [1206]  (hidden comment: 20000)  (no BOM)
R232  value 301k  [1206]  (hidden comment: 301000)
R235  value 0  [1206]  (hidden comment: 0_jumper)  (no BOM)
SW1  MSS420004  [MSS420004]
TP5  value Yellow  [TP_COMPACT]  (hidden comment: TP_5009)
TP6  value Orange  [TP_COMPACT]  (hidden comment: TP_5008)
TP7  value Yellow  [TP_COMPACT]  (hidden comment: TP_5009)
TP8  value Orange  [TP_COMPACT]  (hidden comment: TP_5008)
TP16  value White  [TP_COMPACT]  (hidden comment: TP_5007)
U3  OPA4277UA  [SOIC_14_Narrow]  (parts A,B,C,D of 4)
U4  OPA4277UA  [SOIC_14_Narrow]  (parts A,B,C,D of 4)
U17  TLP281-4  [SOIC_16_C5.85]  (part C of 4)

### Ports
Dec_Lab_Select (bidir), Dec_Vel_Feedback (out), North_Tach+ (in), North_Tach- (in), North_Tach_Out (out), North_Vel_In (in), North_Vel_Out (out), South_Tach+ (in), South_Tach- (in), South_Tach_Out (out), South_Vel_In (in), South_Vel_Out (out)

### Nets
+5_VREF: R35.2
+15V: C10.2 C12.2 R110.2 U3.4(V+) U4.4(V+)
-5_VREF: R231.1
-15V: C68.2 C71.2 U3.11(V-) U4.11(V-)
AGND: C6.1 C7.1 C10.1 C12.1 C55.1 C58.1 C59.1 C60.1 C67.1 C68.1 C71.1 C76.1 D19.A D24.A R23.1 R38.1 R204.1 R205.2 R227.1 SW1.7 U3.5(IN+) U3.10(IN+) U4.5(IN+) U4.10(IN+) U4.12(IN+)
DGND: U17.11(E)
Dec Vel Feedback: R226.2 TP16.1 U3.14(OUT) ; port Dec_Vel_Feedback
Dec_Lab_Select: U17.12(C) ; port Dec_Lab_Select
North Drive+: C60.2 R10.1 TP6.1 ; port North_Tach+
North Drive-: C59.2 R9.1 TP5.1 ; port North_Tach-
North Tach Out: C11.1 C13.1 R44.2 R218.1 R219.1 U3.1(OUT) ; port North_Tach_Out
North Vel In: R19.1 ; port North_Vel_In
North Vel Out: C76.2 R36.2 ; port North_Vel_Out
South Drive+: C55.2 R12.1 TP8.1 ; port South_Tach+
South Drive-: C58.2 R11.1 TP7.1 ; port South_Tach-
South Tach Out: C9.1 C66.1 R26.1 R37.1 R211.1 U4.1(OUT) ; port South_Tach_Out
South Vel In: R230.2 ; port South_Vel_In
South Vel Out: C67.2 R215.2 ; port South_Vel_Out
NetC6_2: C6.2 D4.K D16.A R10.2 R204.2 U3.3(IN+)
NetC7_2: C7.2 D2.K D17.A R12.2 R205.1 U4.3(IN+)
NetC9_2: C9.2 D2.A D17.K R11.2 R26.2 U4.2(IN-)
NetC11_2: C11.2 D4.A D16.K R9.2 R219.2 U3.2(IN-)
NetC13_2: C13.2 R34.1 R218.2
NetC14_1: C14.1 C70.1 R31.1 R37.2 R44.1 U4.9(IN-)
NetC14_2: C14.2 C70.2 R31.2 R48.1 U4.8(OUT)
NetC17_1: C17.1 R41.1 R228.2 R230.1 R232.1 SW1.10 U4.13(IN-)
NetC17_2: C17.2 D7.K D25.A U4.14(OUT)
NetC64_1: C64.1 R19.2 R20.1 R21.1 R235.2 SW1.1 U3.6(IN-)
NetC64_2: C64.2 D6.K D21.A U3.7(OUT)
NetC65_1: C65.1 R222.2
NetC65_2: C65.2 R228.1 SW1.11
NetC66_2: C66.2 R211.2 R222.1
NetC69_1: C69.1 R34.2
NetC69_2: C69.2 R235.1 SW1.2
NetD6_A: D6.A R21.2
NetD7_A: D7.A R41.2 R214.1
NetD19_K: D19.K R22.2 R28.2
NetD21_K: D21.K R20.2 R30.1
NetD24_K: D24.K R40.2 R229.2
NetD25_K: D25.K R232.2
NetR18_1: R18.1 R214.2 U4.6(IN-)
NetR18_2: R18.2 R22.1 R23.2 R215.1
NetR28_1: R28.1 U4.7(OUT)
NetR30_2: R30.2 R39.1 U3.9(IN-)
NetR33_1: R33.1 R35.1 R231.2
NetR33_2: R33.2 R227.2 U3.12(IN+)
NetR36_1: R36.1 R38.2 R39.2 R229.1
NetR40_1: R40.1 U3.8(OUT)
NetR48_2: R48.2 R226.1 U3.13(IN-)
NetR110_1: R110.1 U17.5(A)
NetSW1_8: SW1.8 U17.6(K)

Not connected (* = marked no-connect by the designer): SW1 3 4 5 6 9 12

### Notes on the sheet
- (near TP6) Note: silkscreen "N-" & "N+"
- (near C59) Note: Nominally 8.78 mV/(arcsec/s)
- (near R235) Note: silkscreen labels.
- (near SW1) "SUMMIT"
- (near TP16) Note: silkscreen "Dec Vel"
- 114 (arcsec/s)/V
- (near SW1) NC
- NC
- Note: 1.7mV/(arcsec/s)
- 588 (arcsec/s)/V
- (near SW1) "LAB"
- (near TP8) Note: silkscreen "S-" & "S+"
- (near C58) Note: Nominally 8.78 mV/(arcsec/s)
- (near C58) 114 (arcsec/s)/V
- Dec Tachometer & Servo Command

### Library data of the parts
C6 C7 C9 C11 = 0.022uF: Ceramic Chip Capacitor, 0.022uF, 50V, 10%, X7R; Part Number: C1206C223K5RACTU; Manufacturer: Kemet; BOM_IGNORE: False
C10 C12 C55 C58-C60 C67 C68 C71 C76 = 0.1uF: Ceramic Chip Capacitor, 0.1uF, 50V, 10%, X7R; Part Number: C1206C104K5RACTU; Manufacturer: Kemet; BOM_IGNORE: False
C13 C66 = 0.068uF: Ceramic Chip Capacitor, 0.068uF, 50V, 10%, X7R; Part Number: C1206C683K1RACTU; Manufacturer: Kemet; BOM_IGNORE: False
C14 = 0.22uF: Ceramic Chip Capacitor, 0.22uF, 50V, 10%, X7R; Part Number: C1206C224K5RACTU; Manufacturer: Kemet; BOM_IGNORE: False
C17 C64 = 2200pF: Ceramic Chip Capacitor, 2200pF, 50V, 5%, X7R; Part Number: C1206C222K5RACTU; Manufacturer: Kemet; BOM_IGNORE: False
C65 C69 = 0.33uF: Ceramic Chip Capacitor, 0.33uF, 50V, 10%, X7R; Part Number: C1206C334K5RACTU; Manufacturer: Kemet; BOM_IGNORE: False
C70 = 1uF: Ceramic Chip Capacitor, 1uF, 50V, 10%, X7R; Part Number: C1206F105K5RACTU; Manufacturer: Kemet; BOM_IGNORE: False
D2 D4 D6 D7 D16 D17 D21 D25 = RS1DB-13: RECT FAST RECOVERY 200V 1A; Manufacturer: Diodes Inc
D19 D24 = 1SMA10CAT3G: TVS 400W 10V BIDIRECT SMA; Manufacturer: ON Semiconductor
Flag?#1-Flag?#5 = Flag
R9-R12 = 47500: Thick Film Chip Resistor, 47.5k Ohm, 1% Tolerance, 1206 Size, 0.25 W; Part Number: ERJ-8ENF4752V; Manufacturer: Panasonic; Power Rating: 0.25W
R18 R30 R33 R39 R48 R214 = 200000: Thick Film Chip Resistor, 200k Ohm, 1% Tolerance, 1206 Size, 0.25 W; Part Number: ERJ-8ENF2003V; Manufacturer: Panasonic; Power Rating: 0.25W
R19-R21 R41 R230 R232 = 301000: Thick Film Chip Resistor, 301k Ohm, 1% Tolerance, 1206 Size, 0.25 W; Part Number: ERJ-8ENF3013V; Manufacturer: Panasonic; Power Rating: 0.25W
R22 R229 = 6810: Thick Film Chip Resistor, 6.81k Ohm, 1% Tolerance, 1206 Size, 0.25 W; Part Number: ERJ-8ENF6811V; Manufacturer: Panasonic; Power Rating: 0.25W
R23 R38 R110 = 4870: Thick Film Chip Resistor, 4.87k Ohm, 1% Tolerance, 1206 Size, 0.25 W; Part Number: ERJ-8ENF4871V; Manufacturer: Panasonic; Power Rating: 0.25W
R26 R204 R205 R219 = 10000: Thick Film Chip Resistor, 10k Ohm, 1% Tolerance, 1206 Size, 0.25 W; Part Number: ERJ-8ENF1002V; Manufacturer: Panasonic; Power Rating: 0.25W
R28 R40 = 2000: Thick Film Chip Resistor, 2k Ohm, 1% Tolerance, 1206 Size, 0.25 W; Part Number: ERJ-8ENF2001V; Manufacturer: Panasonic; Power Rating: 0.25W
R31 = 33200: Thick Film Chip Resistor, 33.2k Ohm, 1% Tolerance, 1206 Size, 0.25 W; Part Number: ERJ-8ENF3322V; Manufacturer: Panasonic; Power Rating: 0.25W
R34 R222 = 56200: Thick Film Chip Resistor, 56.2k Ohm, 1% Tolerance, 1206 Size, 0.25 W; Part Number: ERJ-8ENF5622V; Manufacturer: Panasonic; Power Rating: 0.25W
R35 R231 = 20000: Thick Film Chip Resistor, 20k Ohm, 1% Tolerance, 1206 Size, 0.25 W; Part Number: ERJ-8ENF2002V; Manufacturer: Panasonic; Power Rating: 0.25W
R36 R215 = 100: Thick Film Chip Resistor, 100 Ohm, 1% Tolerance, 1206 Size, 0.25 W; Part Number: ERJ-8ENF1000V; Manufacturer: Panasonic; Power Rating: 0.25W
R37 R44 R211 R218 = 68100: Thick Film Chip Resistor, 68.1k Ohm, 1% Tolerance, 1206 Size, 0.25 W; Part Number: ERJ-8ENF6812V; Manufacturer: Panasonic; Power Rating: 0.25W
R226 = 182000: Thick Film Chip Resistor, 182k Ohm, 1% Tolerance, 1206 Size, 0.25 W; Part Number: ERJ-8ENF1823V; Manufacturer: Panasonic; Power Rating: 0.25W
R227 R228 R235 = 0_jumper: Thick Film Chip Resistor, 0 Ohm, 1206 Size, 0.25 W; Part Number: ERJ-8GEY0R00V; Manufacturer: Panasonic; Tolerance: 1%; Power Rating: 0.25W
SW1 = MSS420004: Switch, Slide, 4PDT; Manufacturer: Tyco Electronics Alcoswitch
TP5 TP7 = TP_5009: Yellow, Compact Test Point, Thru Hole, Loop; Part Number: 5009; Manufacturer: Keystone; BOM_IGNORE: FALSE
TP6 TP8 = TP_5008: Orange, Compact Test Point, Thru Hole, Loop; Part Number: 5008; Manufacturer: Keystone; BOM_IGNORE: FALSE
TP16 = TP_5007: White, Compact Test Point, Thru Hole, Loop; Part Number: 5007; Manufacturer: Keystone; BOM_IGNORE: FALSE
U3 U4 = OPA4277UA: QUAD PRECISION OPAMP 14-SOIC; Manufacturer: Texas Instruments
U17 = TLP281-4: Photocoupler; Manufacturer: Toshiba

## Sheet SB_PG13.SCHDOC: (Title)
size B; PageSetup: Record=PageOptions|CenterHorizontal=True|CenterVertical=True|PrintScale=1.09|XCorrection=1.00|YCorrection=1.00|PrintKind=0|BorderSize=5000000|LeftOffset=0|BottomOffset=0|Orientation=2|PaperLength=1000|PaperWidth=1000|Scale=100|PaperSource=7|PrintQuality=-4|MediaType=1|DitherType=10|PaperKind=11x17|PrintScaleMode=1; Engineer: (Engineer); Organization: Institute for Astronomy; Address1: 640 N. Aohoku Place; Address2: Hilo, HI 96720; DocumentNumber: T3-2070; Revision: D; SheetNumber: 13; SheetTotal: 16
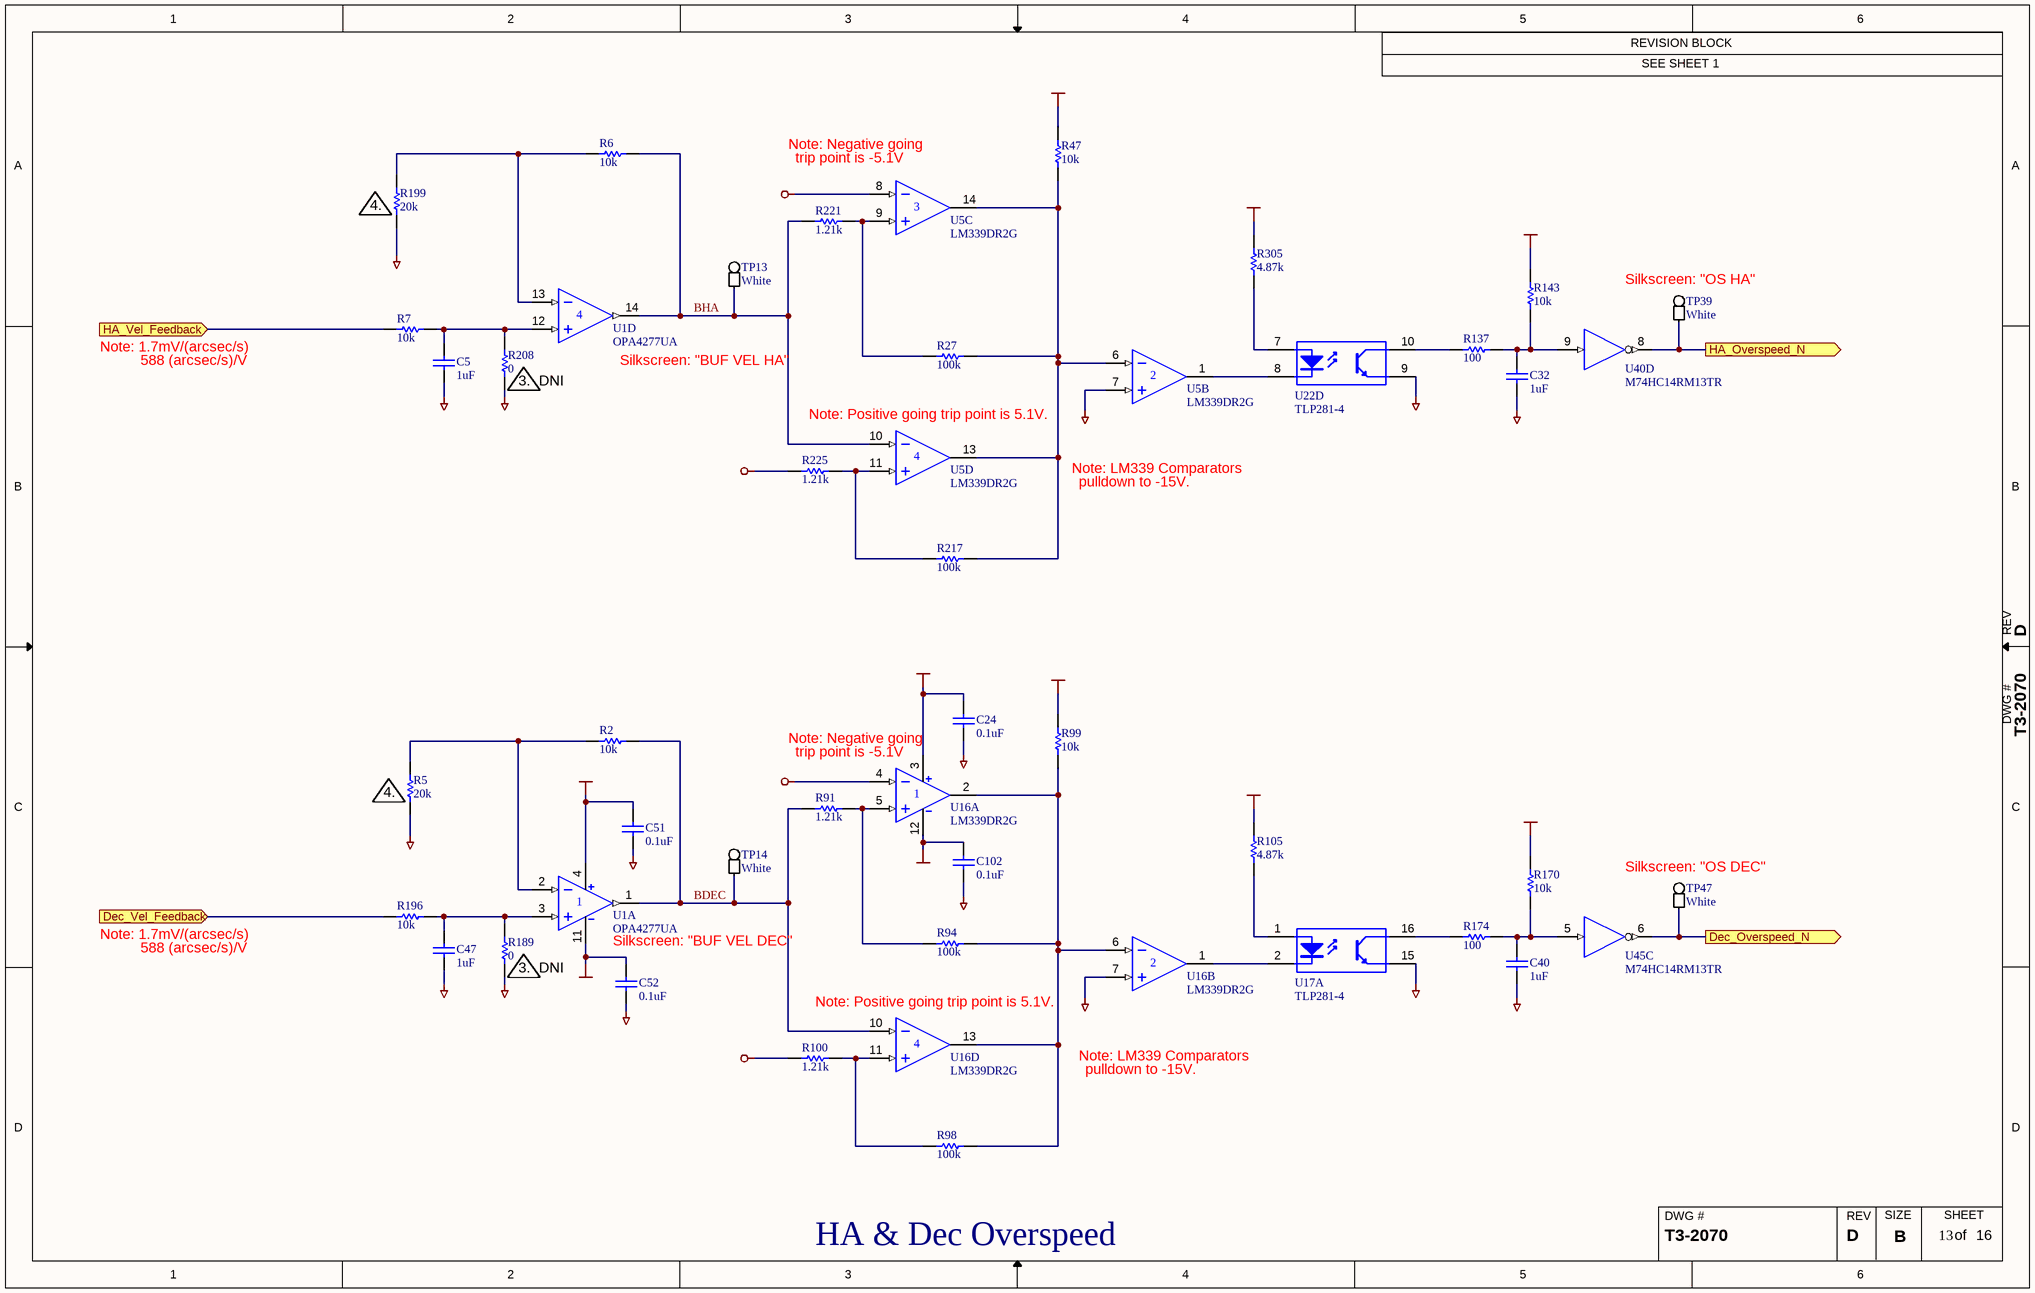
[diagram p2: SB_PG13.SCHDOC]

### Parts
(Parts that share a designator on the sheet are numbered #1, #2 ... from top to bottom, then left to right.)
C5  1uF  [1206]
C24  0.1uF  [1206]
C32  1uF  [1206]
C40  1uF  [1206]
C47  1uF  [1206]
C51  0.1uF  [1206]
C52  0.1uF  [1206]
C102  0.1uF  [1206]
Flag?#6  Flag#: 4.  (hidden comment: Flag)  (graphical)
Flag?#7  Flag#: 3.  Note: DNI  (graphical)
Flag?#8  Flag#: 4.  (hidden comment: Flag)  (graphical)
Flag?#9  Flag#: 3.  Note: DNI  (graphical)
R2  value 10k  [1206]  (hidden comment: 10000)
R5  value 20k  [1206]  (hidden comment: 20000)
R6  value 10k  [1206]  (hidden comment: 10000)
R7  value 10k  [1206]  (hidden comment: 10000)
R27  value 100k  [1206]  (hidden comment: 100000)
R47  value 10k  [1206]  (hidden comment: 10000)
R91  value 1.21k  [1206]  (hidden comment: 1210)
R94  value 100k  [1206]  (hidden comment: 100000)
R98  value 100k  [1206]  (hidden comment: 100000)
R99  value 10k  [1206]  (hidden comment: 10000)
R100  value 1.21k  [1206]  (hidden comment: 1210)
R105  value 4.87k  [1206]  (hidden comment: 4870)
R137  100  [1206]
R143  value 10k  [1206]  (hidden comment: 10000)
R170  value 10k  [1206]  (hidden comment: 10000)
R174  100  [1206]
R189  value 0  [1206]  (hidden comment: 0_jumper)  (no BOM)
R196  value 10k  [1206]  (hidden comment: 10000)
R199  value 20k  [1206]  (hidden comment: 20000)
R208  value 0  [1206]  (hidden comment: 0_jumper)  (no BOM)
R217  value 100k  [1206]  (hidden comment: 100000)
R221  value 1.21k  [1206]  (hidden comment: 1210)
R225  value 1.21k  [1206]  (hidden comment: 1210)
R305  value 4.87k  [1206]  (hidden comment: 4870)
TP13  value White  [TP_COMPACT]  (hidden comment: TP_5007)
TP14  value White  [TP_COMPACT]  (hidden comment: TP_5007)
TP39  value White  [TP_COMPACT]  (hidden comment: TP_5007)
TP47  value White  [TP_COMPACT]  (hidden comment: TP_5007)
U1  OPA4277UA  [SOIC_14_Narrow]  (parts A,D of 4)
U5  LM339DR2G  [SOIC_14_Narrow]  (parts B,C,D of 4)
U16  LM339DR2G  [SOIC_14_Narrow]  (parts A,B,D of 4)
U17  TLP281-4  [SOIC_16_C5.85]  (part A of 4)
U22  TLP281-4  [SOIC_16_C5.85]  (part D of 4)
U40  M74HC14RM13TR  [SOIC_14_Narrow]  (part D of 6)
U45  M74HC14RM13TR  [SOIC_14_Narrow]  (part C of 6)

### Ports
Dec_Overspeed_N (out), Dec_Vel_Feedback (in), HA_Overspeed_N (out), HA_Vel_Feedback (in)

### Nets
+5_VREF: R100.1 R225.1
+5V_DIG: R143.2 R170.2
+15V: C24.2 C51.2 R47.2 R99.2 R105.2 R305.2 U1.4(V+) U16.3(V+)
-5_VREF: U5.8(IN-) U16.4(IN-)
-15V: C52.2 C102.2 U1.11(V-) U16.12(V-)
AGND: C5.1 C24.1 C47.1 C51.1 C52.1 C102.1 R5.1 R189.1 R199.1 R208.1 U5.7(IN+) U16.7(IN+)
DGND: C32.1 C40.1 U17.15(E) U22.9(E)
BDEC: R2.2 R91.1 TP14.1 U1.1(OUT) U16.10(IN-)
BHA: R6.2 R221.1 TP13.1 U1.14(OUT) U5.10(IN-)
Dec Vel Feedback: R196.1 ; port Dec_Vel_Feedback
Dec_Overspeed_N: TP47.1 U45.6(~{OUT}) ; port Dec_Overspeed_N
HA Vel Feedback: R7.1 ; port HA_Vel_Feedback
HA_Overspeed_N: TP39.1 U40.8(~{OUT}) ; port HA_Overspeed_N
NetC5_2: C5.2 R7.2 R208.2 U1.12(IN+)
NetC32_2: C32.2 R137.1 R143.1 U40.9(IN)
NetC40_2: C40.2 R170.1 R174.1 U45.5(IN)
NetC47_2: C47.2 R189.2 R196.2 U1.3(IN+)
NetR2_1: R2.1 R5.2 U1.2(IN-)
NetR6_1: R6.1 R199.2 U1.13(IN-)
NetR27_1: R27.1 R221.2 U5.9(IN+)
NetR27_2: R27.2 R47.1 R217.2 U5.6(IN-) U5.13(OUT) U5.14(OUT)
NetR91_2: R91.2 R94.1 U16.5(IN+)
NetR94_2: R94.2 R98.2 R99.1 U16.2(OUT) U16.6(IN-) U16.13(OUT)
NetR98_1: R98.1 R100.2 U16.11(IN+)
NetR105_1: R105.1 U17.1(A)
NetR137_2: R137.2 U22.10(C)
NetR174_2: R174.2 U17.16(C)
NetR217_1: R217.1 R225.2 U5.11(IN+)
NetR305_1: R305.1 U22.7(A)
NetU5_1: U5.1(OUT) U22.8(K)
NetU16_1: U16.1(OUT) U17.2(K)

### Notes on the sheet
- (near U5) Note: Negative going
- (near U5) trip point is -5.1V
- (near TP39) Silkscreen: "OS HA"
- Note: 1.7mV/(arcsec/s)
- 588 (arcsec/s)/V
- (near U1) Silkscreen: "BUF VEL HA"
- (near U5) Note: Positive going trip point is 5.1V.
- Note: LM339 Comparators
- pulldown to -15V.
- Note: Negative going
- (near U16) trip point is -5.1V
- (near TP47) Silkscreen: "OS DEC"
- Silkscreen: "BUF VEL DEC"
- (near U16) Note: Positive going trip point is 5.1V.
- HA & Dec Overspeed

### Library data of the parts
C5 C32 C40 C47 = 1uF: as C70 on sheet SB_PG4
C24 C51 C52 C102 = 0.1uF: as C10 on sheet SB_PG4
Flag?#7 Flag?#9 = Flag
R2 R6 R7 R47 R99 R143 R170 R196 = 10000: as R26 on sheet SB_PG4
R5 R199 = 20000: as R35 on sheet SB_PG4
R27 R94 R98 R217 = 100000: Thick Film Chip Resistor, 100k Ohm, 1% Tolerance, 1206 Size, 0.25 W; Part Number: ERJ-8ENF1003V; Manufacturer: Panasonic; Power Rating: 0.25W
R91 R100 R221 R225 = 1210: Thick Film Chip Resistor, 1.21k Ohm, 1% Tolerance, 1206 Size, 0.25 W; Part Number: ERJ-8ENF1211V; Manufacturer: Panasonic; Power Rating: 0.25W
R105 R305 = 4870: as R23 on sheet SB_PG4
R137 R174 = 100: as R36 on sheet SB_PG4
R189 R208 = 0_jumper: as R227 on sheet SB_PG4
TP13 TP14 TP39 TP47 = TP_5007: as TP16 on sheet SB_PG4
U1 = OPA4277UA: as U3 on sheet SB_PG4
U5 U16 = LM339DR2G: Quad Comparator; Manufacturer: ON Semiconductor
U17 U22 = TLP281-4: Photocoupler; Manufacturer: Toshiba
U40 U45 = M74HC14RM13TR: Hex Schmitt-Trigger Inverter; Manufacturer: STMicroelectronics

## Sheet SB_PG5.SCHDOC: (Title)
size B; PageSetup: Record=PageOptions|CenterHorizontal=True|CenterVertical=True|PrintScale=0.70|XCorrection=1.00|YCorrection=1.00|PrintKind=0|BorderSize=5000000|LeftOffset=0|BottomOffset=0|Orientation=2|PaperLength=1000|PaperWidth=1000|Scale=100|PaperSource=7|PrintQuality=-4|MediaType=1|DitherType=10|PaperKind=Letter|PrintScaleMode=1; Engineer: (Engineer); Organization: Institute for Astronomy; Address1: 640 N. Aohoku Place; Address2: Hilo, HI 96720; DocumentNumber: T3-2070; Revision: D; SheetNumber: 5; SheetTotal: 16
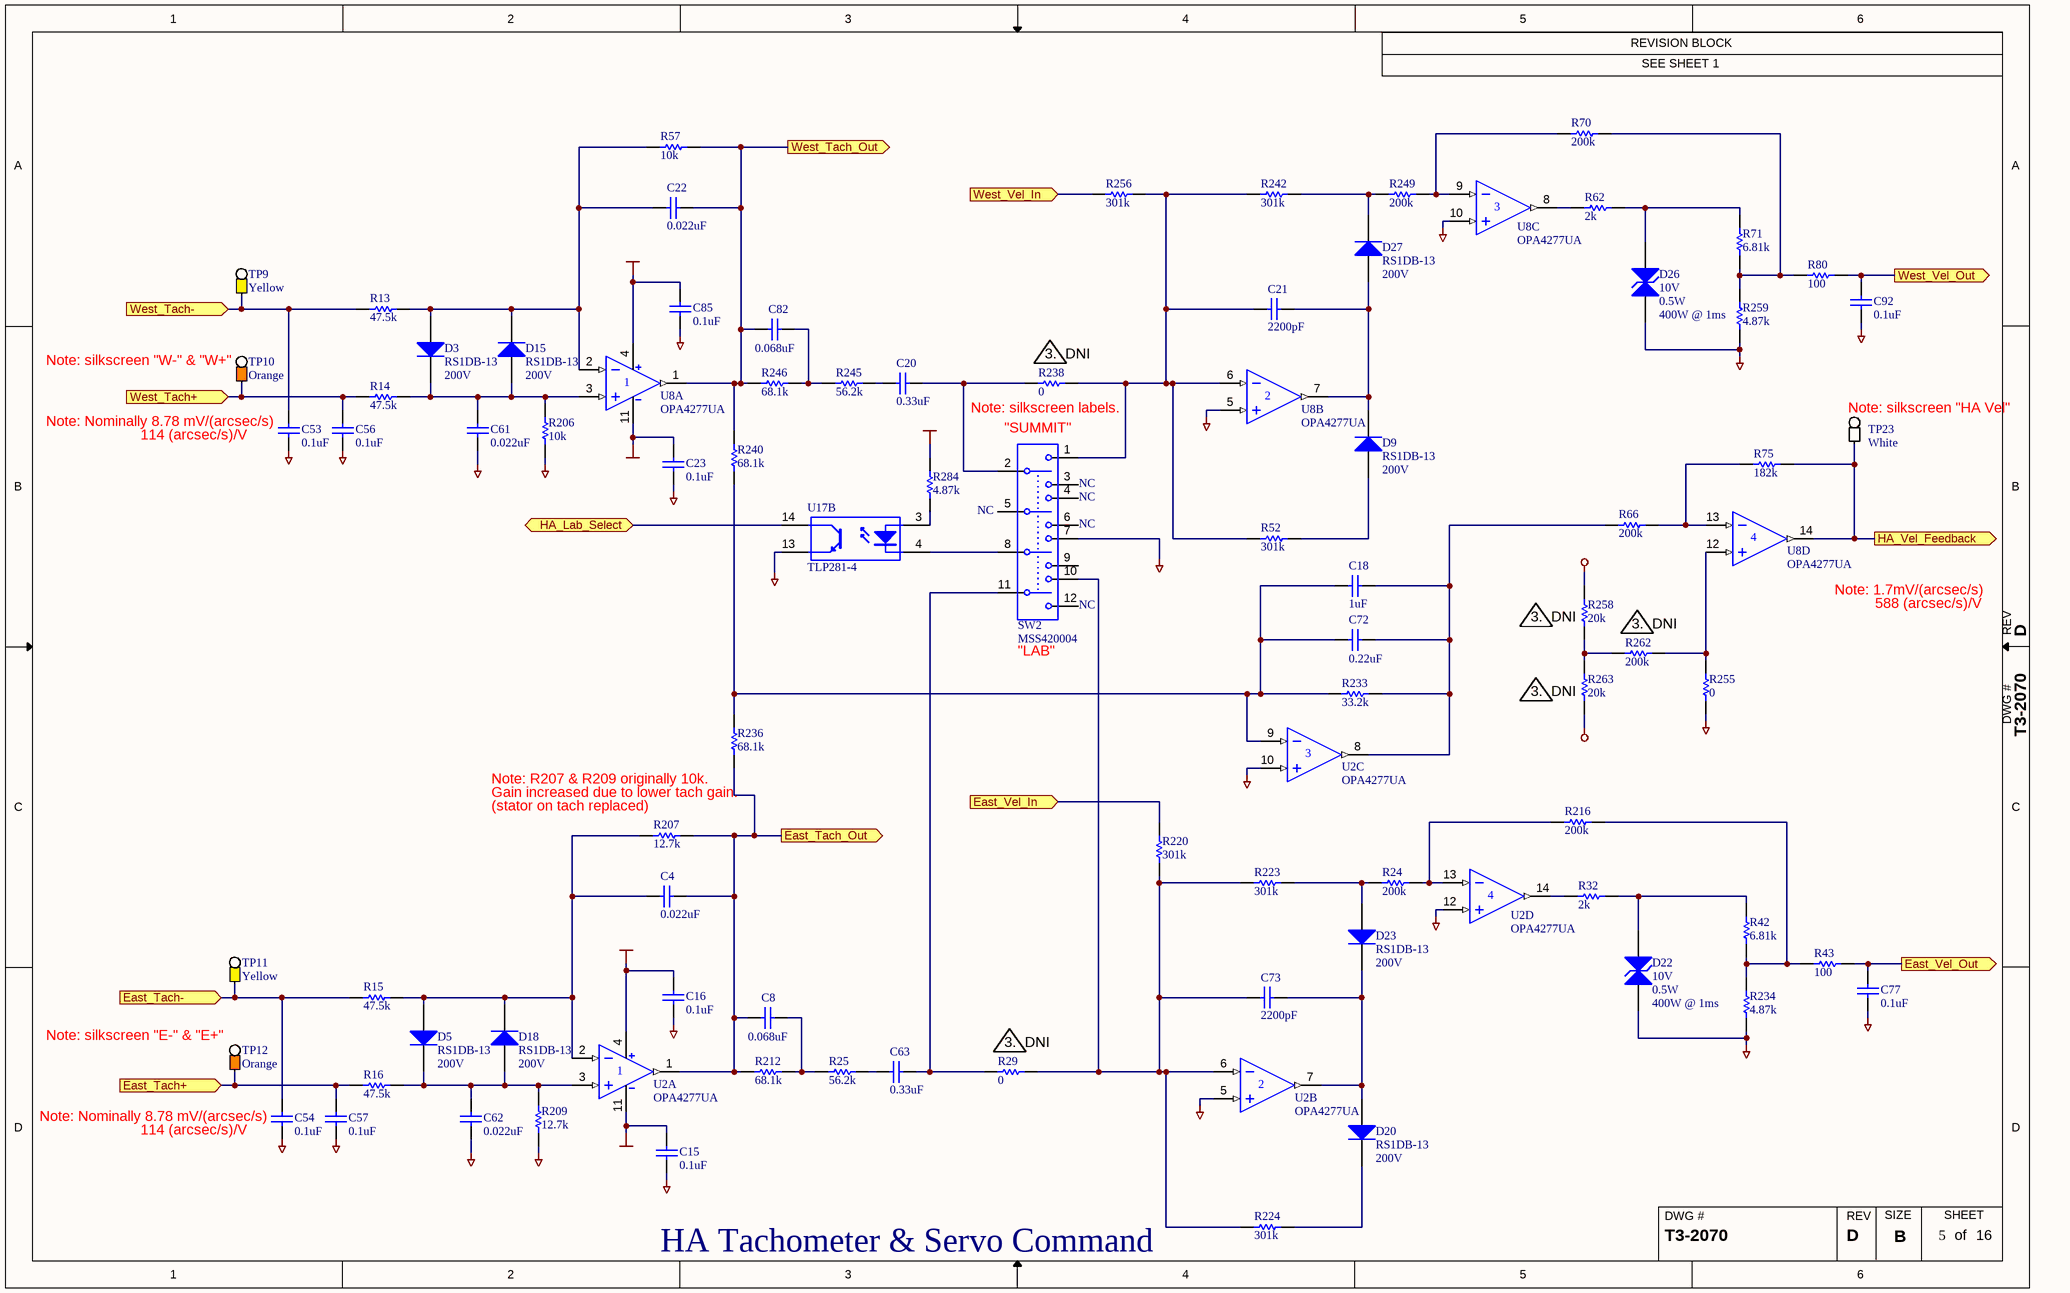
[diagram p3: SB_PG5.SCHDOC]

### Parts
(Parts that share a designator on the sheet are numbered #1, #2 ... from top to bottom, then left to right.)
C4  0.022uF  [1206]
C8  0.068uF  [1206]
C15  0.1uF  [1206]
C16  0.1uF  [1206]
C18  1uF  [1206]
C20  0.33uF  [1206]
C21  2200pF  [1206]
C22  0.022uF  [1206]
C23  0.1uF  [1206]
C53  0.1uF  [1206]
C54  0.1uF  [1206]
C56  0.1uF  [1206]
C57  0.1uF  [1206]
C61  0.022uF  [1206]
C62  0.022uF  [1206]
C63  0.33uF  [1206]
C72  0.22uF  [1206]
C73  2200pF  [1206]
C77  0.1uF  [1206]
C82  0.068uF  [1206]
C85  0.1uF  [1206]
C92  0.1uF  [1206]
D3  Voltage: 200V  [DO-214AA (SMB) & MARKING]  (hidden comment: RS1DB-13)
D5  Voltage: 200V  [DO-214AA (SMB) & MARKING]  (hidden comment: RS1DB-13)
D9  Voltage: 200V  [DO-214AA (SMB) & MARKING]  (hidden comment: RS1DB-13)
D15  Voltage: 200V  [DO-214AA (SMB) & MARKING]  (hidden comment: RS1DB-13)
D18  Voltage: 200V  [DO-214AA (SMB) & MARKING]  (hidden comment: RS1DB-13)
D20  Voltage: 200V  [DO-214AA (SMB) & MARKING]  (hidden comment: RS1DB-13)
D22  value 10V  Power: 0.5W  Peak Power: 400W @ 1ms  [DO-214AC (SMA)]  (hidden comment: 1SMA10CAT3G)
D23  Voltage: 200V  [DO-214AA (SMB) & MARKING]  (hidden comment: RS1DB-13)
D26  value 10V  Power: 0.5W  Peak Power: 400W @ 1ms  [DO-214AC (SMA)]  (hidden comment: 1SMA10CAT3G)
D27  Voltage: 200V  [DO-214AA (SMB) & MARKING]  (hidden comment: RS1DB-13)
Flag?#10  Flag#: 3.  Note: DNI  (graphical)
Flag?#11  Flag#: 3.  Note: DNI  (graphical)
Flag?#12  Flag#: 3.  Note: DNI  (graphical)
Flag?#13  Flag#: 3.  Note: DNI  (graphical)
Flag?#14  Flag#: 3.  Note: DNI  (graphical)
R13  value 47.5k  [1206]  (hidden comment: 47500)
R14  value 47.5k  [1206]  (hidden comment: 47500)
R15  value 47.5k  [1206]  (hidden comment: 47500)
R16  value 47.5k  [1206]  (hidden comment: 47500)
R24  value 200k  [1206]  (hidden comment: 200000)
R25  value 56.2k  [1206]  (hidden comment: 56200)
R29  value 0  [1206]  (hidden comment: 0_jumper)  (no BOM)
R32  value 2k  [1206]  (hidden comment: 2000)
R42  value 6.81k  [1206]  (hidden comment: 6810)
R43  100  [1206]
R52  value 301k  [1206]  (hidden comment: 301000)
R57  value 10k  [1206]  (hidden comment: 10000)
R62  value 2k  [1206]  (hidden comment: 2000)
R66  value 200k  [1206]  (hidden comment: 200000)
R70  value 200k  [1206]  (hidden comment: 200000)
R71  value 6.81k  [1206]  (hidden comment: 6810)
R75  value 182k  [1206]  (hidden comment: 182000)
R80  100  [1206]
R206  value 10k  [1206]  (hidden comment: 10000)
R207  value 12.7k  [1206]  (hidden comment: 12700)
R209  value 12.7k  [1206]  (hidden comment: 12700)
R212  value 68.1k  [1206]  (hidden comment: 68100)
R216  value 200k  [1206]  (hidden comment: 200000)
R220  value 301k  [1206]  (hidden comment: 301000)
R223  value 301k  [1206]  (hidden comment: 301000)
R224  value 301k  [1206]  (hidden comment: 301000)
R233  value 33.2k  [1206]  (hidden comment: 33200)
R234  value 4.87k  [1206]  (hidden comment: 4870)
R236  value 68.1k  [1206]  (hidden comment: 68100)
R238  value 0  [1206]  (hidden comment: 0_jumper)  (no BOM)
R240  value 68.1k  [1206]  (hidden comment: 68100)
R242  value 301k  [1206]  (hidden comment: 301000)
R245  value 56.2k  [1206]  (hidden comment: 56200)
R246  value 68.1k  [1206]  (hidden comment: 68100)
R249  value 200k  [1206]  (hidden comment: 200000)
R255  value 0  [1206]  (hidden comment: 0_jumper)
R256  value 301k  [1206]  (hidden comment: 301000)
R258  value 20k  [1206]  (hidden comment: 20000)  (no BOM)
R259  value 4.87k  [1206]  (hidden comment: 4870)
R262  value 200k  [1206]  (hidden comment: 200000)  (no BOM)
R263  value 20k  [1206]  (hidden comment: 20000)  (no BOM)
R284  value 4.87k  [1206]  (hidden comment: 4870)
SW2  MSS420004  [MSS420004]
TP9  value Yellow  [TP_COMPACT]  (hidden comment: TP_5009)
TP10  value Orange  [TP_COMPACT]  (hidden comment: TP_5008)
TP11  value Yellow  [TP_COMPACT]  (hidden comment: TP_5009)
TP12  value Orange  [TP_COMPACT]  (hidden comment: TP_5008)
TP23  value White  [TP_COMPACT]  (hidden comment: TP_5007)
U2  OPA4277UA  [SOIC_14_Narrow]  (parts A,B,C,D of 4)
U8  OPA4277UA  [SOIC_14_Narrow]  (parts A,B,C,D of 4)
U17  TLP281-4  [SOIC_16_C5.85]  (part B of 4)

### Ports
East_Tach+ (in), East_Tach- (in), East_Tach_Out (out), East_Vel_In (in), East_Vel_Out (out), HA_Lab_Select (bidir), HA_Vel_Feedback (out), West_Tach+ (in), West_Tach- (in), West_Tach_Out (out), West_Vel_In (in), West_Vel_Out (out)

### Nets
+5_VREF: R258.2
+15V: C16.2 C85.2 R284.2 U2.4(V+) U8.4(V+)
-5_VREF: R263.1
-15V: C15.2 C23.2 U2.11(V-) U8.11(V-)
AGND: C15.1 C16.1 C23.1 C53.1 C54.1 C56.1 C57.1 C61.1 C62.1 C77.1 C85.1 C92.1 D22.A D26.A R206.1 R209.1 R234.1 R255.1 R259.1 SW2.7 U2.5(IN+) U2.10(IN+) U2.12(IN+) U8.5(IN+) U8.10(IN+)
DGND: U17.13(E)
Dec_Lab_Select: U17.14(C) ; port HA_Lab_Select
East Drive+: C57.2 R16.1 TP12.1 ; port East_Tach+
East Drive-: C54.2 R15.1 TP11.1 ; port East_Tach-
East Tach Out: C4.1 C8.1 R207.1 R212.1 R236.1 U2.1(OUT) ; port East_Tach_Out
East Vel In: R220.2 ; port East_Vel_In
East Vel Out: C77.2 R43.2 ; port East_Vel_Out
HA Vel Feedback: R75.2 TP23.1 U8.14(OUT) ; port HA_Vel_Feedback
West Drive+: C56.2 R14.1 TP10.1 ; port West_Tach+
West Drive-: C53.2 R13.1 TP9.1 ; port West_Tach-
West Tach Out: C22.1 C82.1 R57.2 R240.2 R246.1 U8.1(OUT) ; port West_Tach_Out
West Vel In: R256.1 ; port West_Vel_In
West Vel Out: C92.2 R80.2 ; port West_Vel_Out
NetC4_2: C4.2 D5.A D18.K R15.2 R207.2 U2.2(IN-)
NetC8_2: C8.2 R25.1 R212.2
NetC18_1: C18.1 C72.1 R233.1 R236.2 R240.1 U2.9(IN-)
NetC18_2: C18.2 C72.2 R66.1 R233.2 U2.8(OUT)
NetC20_1: C20.1 R245.2
NetC20_2: C20.2 R238.1 SW2.2
NetC21_1: C21.1 R52.1 R238.2 R242.1 R256.2 SW2.1 U8.6(IN-)
NetC21_2: C21.2 D9.K D27.A U8.7(OUT)
NetC22_2: C22.2 D3.A D15.K R13.2 R57.1 U8.2(IN-)
NetC61_2: C61.2 D3.K D15.A R14.2 R206.2 U8.3(IN+)
NetC62_2: C62.2 D5.K D18.A R16.2 R209.2 U2.3(IN+)
NetC63_1: C63.1 R25.2
NetC63_2: C63.2 R29.1 SW2.11
NetC73_1: C73.1 R29.2 R220.1 R223.1 R224.1 SW2.10 U2.6(IN-)
NetC73_2: C73.2 D20.A D23.K U2.7(OUT)
NetC82_2: C82.2 R245.1 R246.2
NetD9_A: D9.A R52.2
NetD20_K: D20.K R224.2
NetD22_K: D22.K R32.2 R42.2
NetD23_A: D23.A R24.1 R223.2
NetD26_K: D26.K R62.2 R71.2
NetD27_K: D27.K R242.2 R249.1
NetR24_2: R24.2 R216.1 U2.13(IN-)
NetR32_1: R32.1 U2.14(OUT)
NetR42_1: R42.1 R43.1 R216.2 R234.2
NetR62_1: R62.1 U8.8(OUT)
NetR66_2: R66.2 R75.1 U8.13(IN-)
NetR70_1: R70.1 R249.2 U8.9(IN-)
NetR70_2: R70.2 R71.1 R80.1 R259.2
NetR255_2: R255.2 R262.2 U8.12(IN+)
NetR258_1: R258.1 R262.1 R263.2
NetR284_1: R284.1 U17.3(A)
NetSW2_8: SW2.8 U17.4(K)

Not connected (* = marked no-connect by the designer): SW2 3 4 5 6 9 12

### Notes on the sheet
- (near TP10) Note: silkscreen "W-" & "W+"
- (near C53) Note: Nominally 8.78 mV/(arcsec/s)
- (near R238) Note: silkscreen labels.
- (near SW2) "SUMMIT"
- (near TP23) Note: silkscreen "HA Vel"
- 114 (arcsec/s)/V
- (near SW2) NC
- NC
- Note: 1.7mV/(arcsec/s)
- 588 (arcsec/s)/V
- (near SW2) "LAB"
- (near R236) Note: R207 & R209 originally 10k.
- Gain increased due to lower tach gain.
- (near R207) (stator on tach replaced)
- (near TP12) Note: silkscreen "E-" & "E+"
- (near C54) Note: Nominally 8.78 mV/(arcsec/s)
- (near C54) 114 (arcsec/s)/V
- HA Tachometer & Servo Command

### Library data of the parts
C4 C22 C61 C62 = 0.022uF: as C6 on sheet SB_PG4
C8 C82 = 0.068uF: as C13 on sheet SB_PG4
C15 C16 C23 C53 C54 C56 C57 C77 C85 C92 = 0.1uF: as C10 on sheet SB_PG4
C18 = 1uF: as C70 on sheet SB_PG4
C20 C63 = 0.33uF: as C65 on sheet SB_PG4
C21 C73 = 2200pF: as C17 on sheet SB_PG4
C72 = 0.22uF: as C14 on sheet SB_PG4
D3 D5 D9 D15 D18 D20 D23 D27 = RS1DB-13: as D2 on sheet SB_PG4
D22 D26 = 1SMA10CAT3G: as D19 on sheet SB_PG4
Flag?#10-Flag?#14 = Flag
R13-R16 = 47500: as R9 on sheet SB_PG4
R24 R66 R70 R216 R249 R262 = 200000: as R18 on sheet SB_PG4
R25 R245 = 56200: as R34 on sheet SB_PG4
R29 R238 R255 = 0_jumper: as R227 on sheet SB_PG4
R32 R62 = 2000: as R28 on sheet SB_PG4
R42 R71 = 6810: as R22 on sheet SB_PG4
R43 R80 = 100: as R36 on sheet SB_PG4
R52 R220 R223 R224 R242 R256 = 301000: as R19 on sheet SB_PG4
R57 R206 = 10000: as R26 on sheet SB_PG4
R75 = 182000: as R226 on sheet SB_PG4
R207 R209 = 12700: Thick Film Chip Resistor, 12.7k Ohm, 1% Tolerance, 1206 Size, 0.25 W; Part Number: ERJ-8ENF1272V; Manufacturer: Panasonic; Power Rating: 0.25W
R212 R236 R240 R246 = 68100: as R37 on sheet SB_PG4
R233 = 33200: as R31 on sheet SB_PG4
R234 R259 R284 = 4870: as R23 on sheet SB_PG4
R258 R263 = 20000: as R35 on sheet SB_PG4
SW2 = MSS420004: as SW1 on sheet SB_PG4
TP9 TP11 = TP_5009: as TP5 on sheet SB_PG4
TP10 TP12 = TP_5008: as TP6 on sheet SB_PG4
TP23 = TP_5007: as TP16 on sheet SB_PG4
U2 U8 = OPA4277UA: as U3 on sheet SB_PG4
U17 = TLP281-4: Photocoupler; Manufacturer: Toshiba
